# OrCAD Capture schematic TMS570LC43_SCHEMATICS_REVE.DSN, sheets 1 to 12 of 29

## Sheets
1 PAGE08: MCU NHET: size B; title: TMS570LC43x HDK; rev: B; company: Texas Instruments Inc; note: MCU NHET
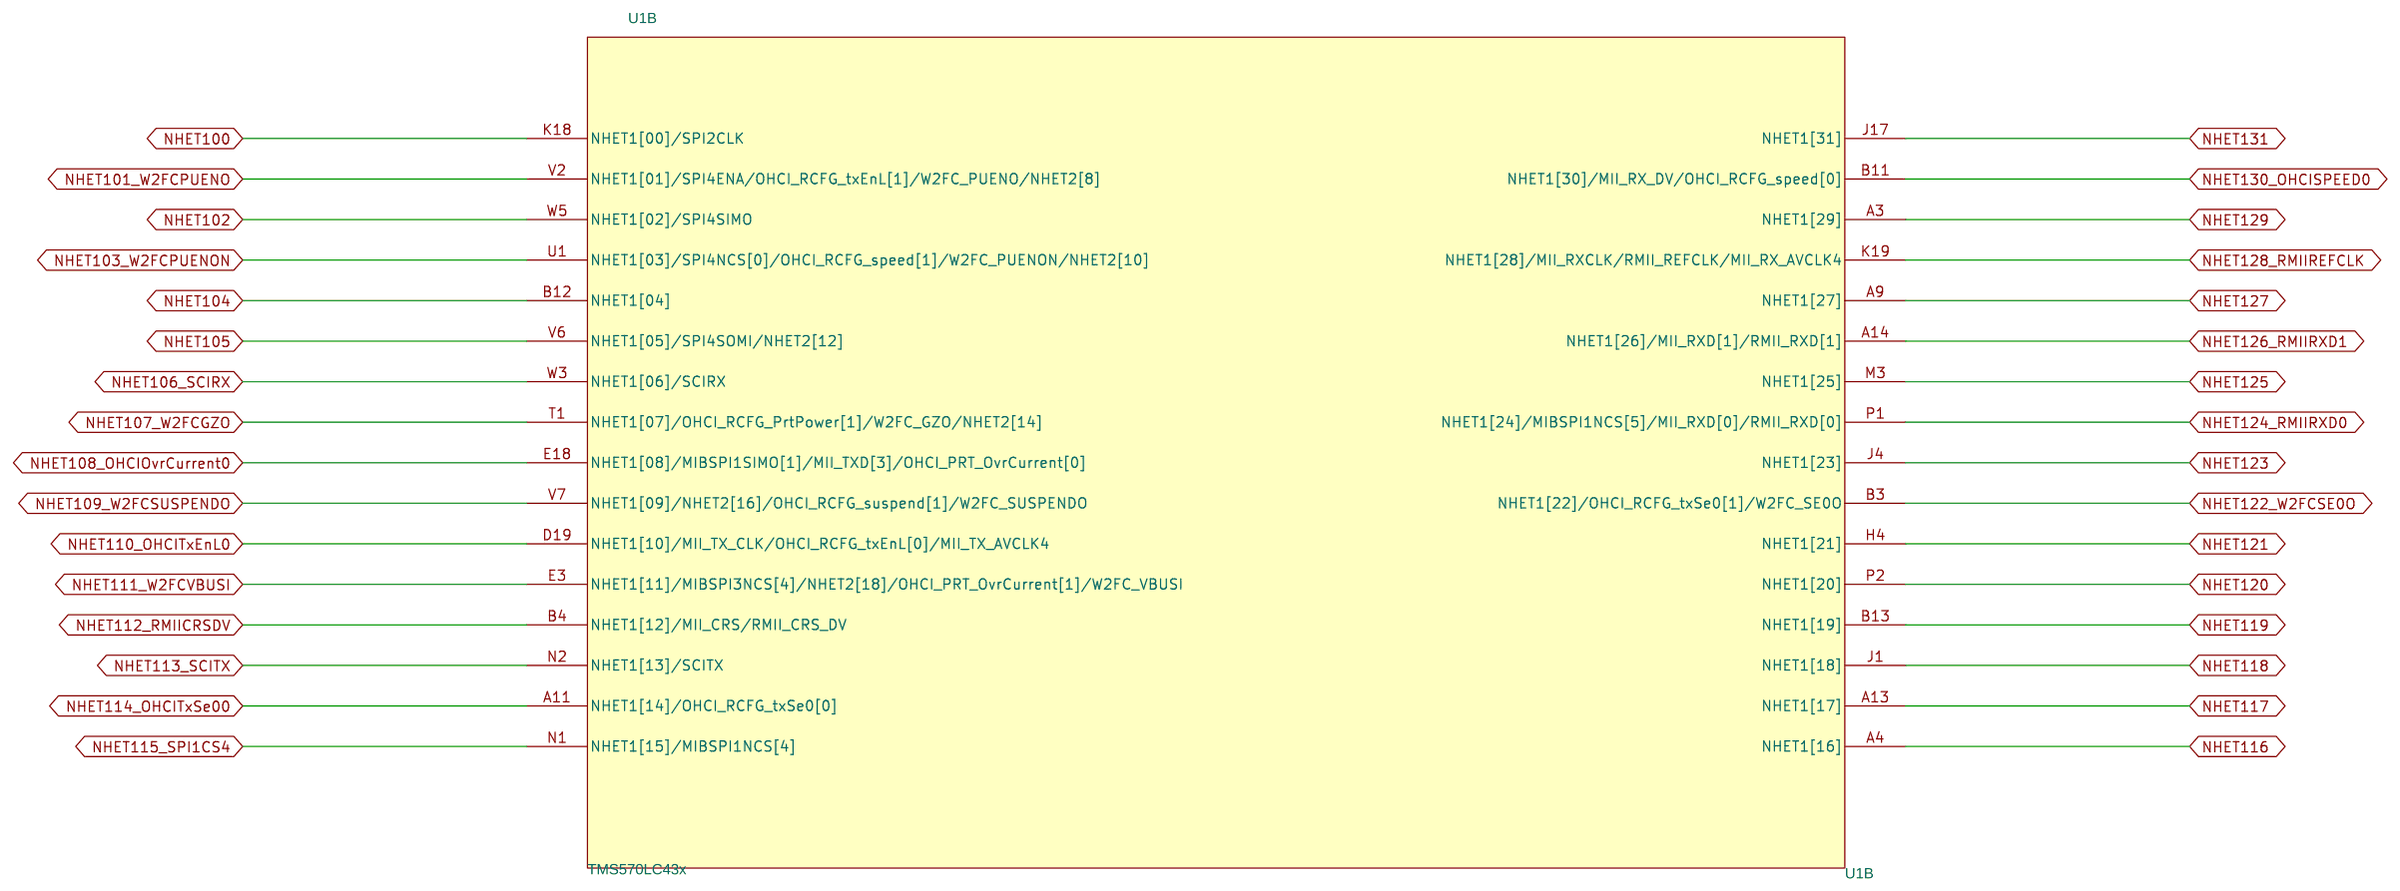
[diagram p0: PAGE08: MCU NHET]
2 PAGE29: EXP P3: size B; note: Expansion Connector 2
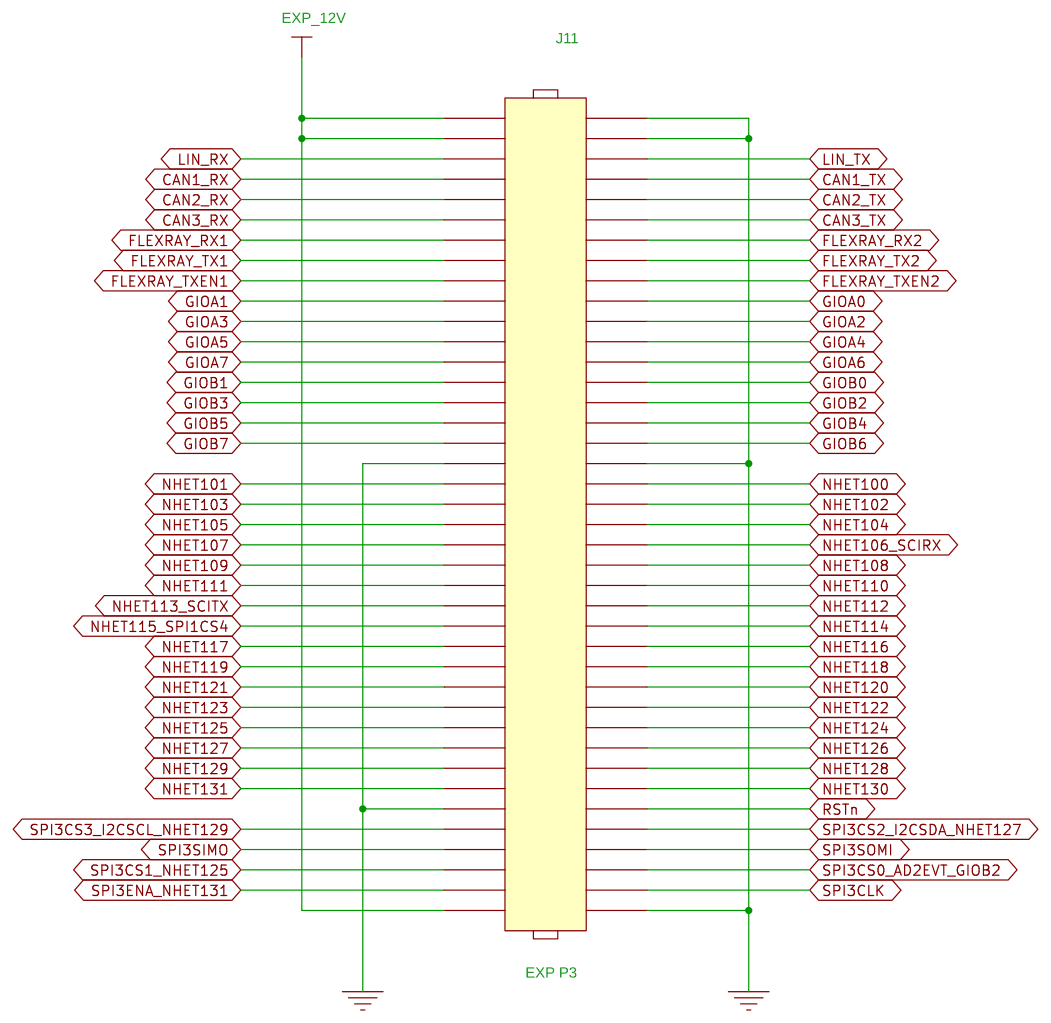
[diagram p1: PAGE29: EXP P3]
3 PAGE13: SDRAM: size B; note: SDRAM
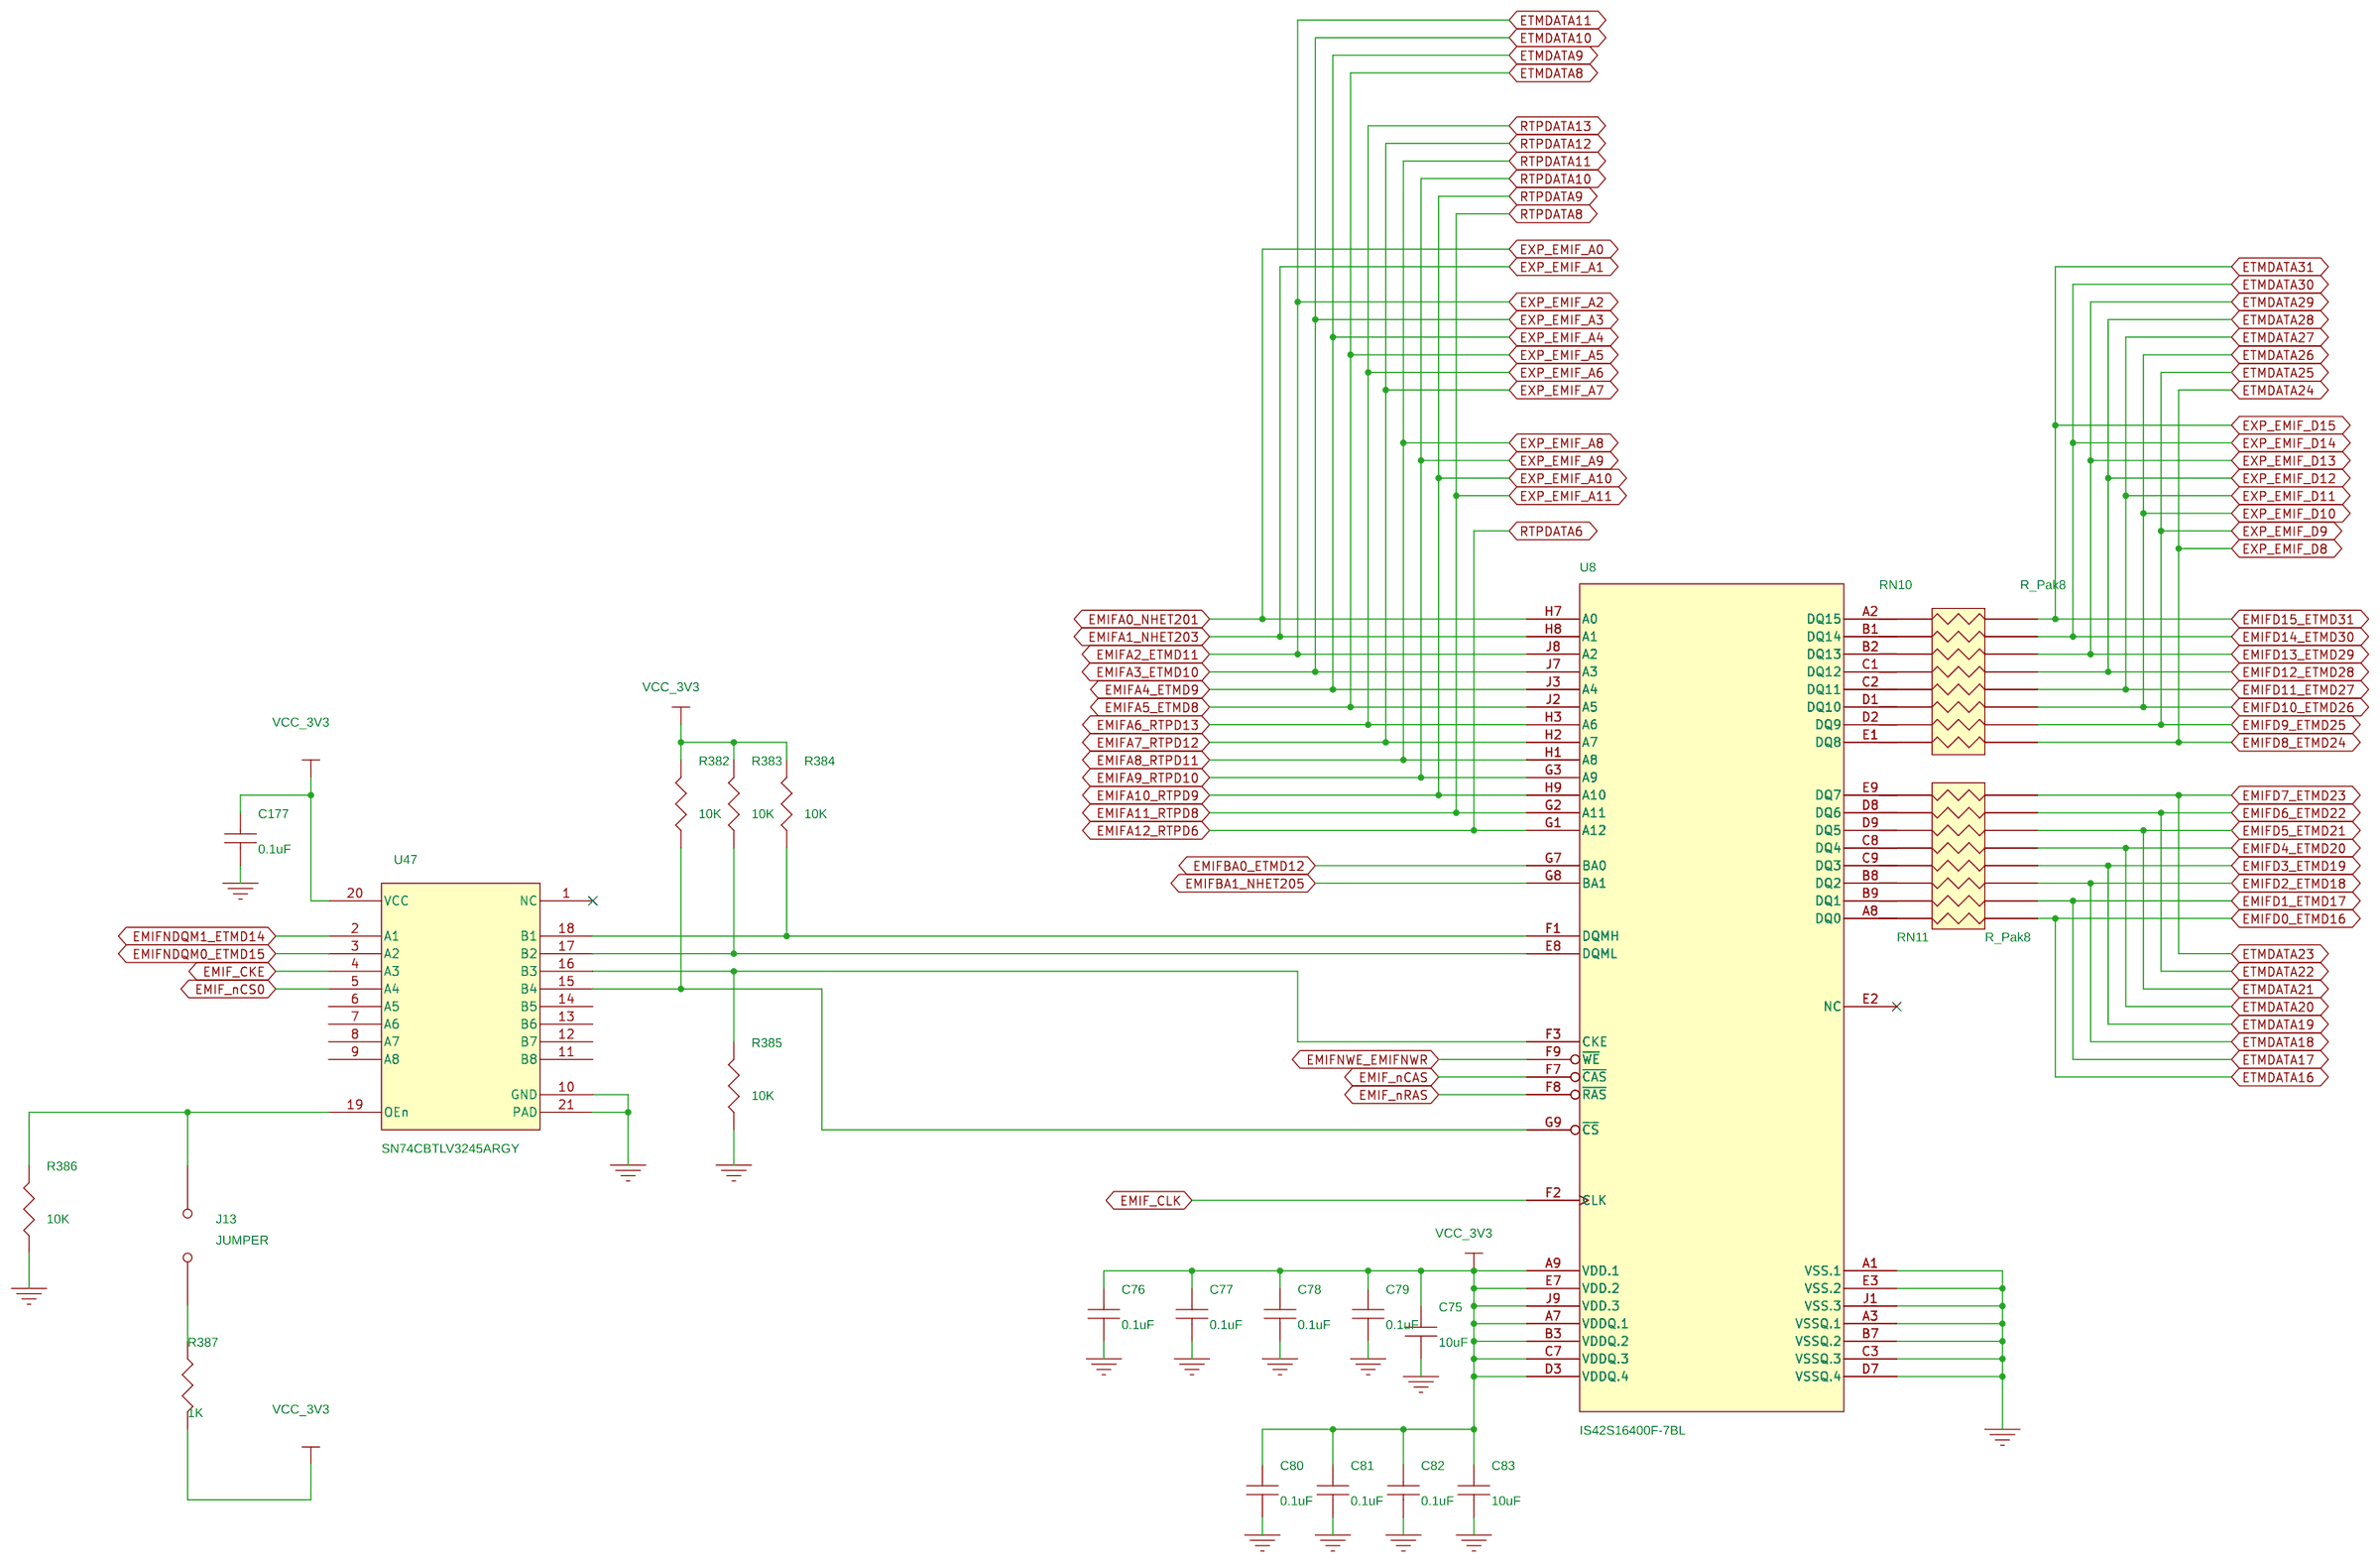
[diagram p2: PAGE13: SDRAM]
4 PAGE01: Title: note: TITLE
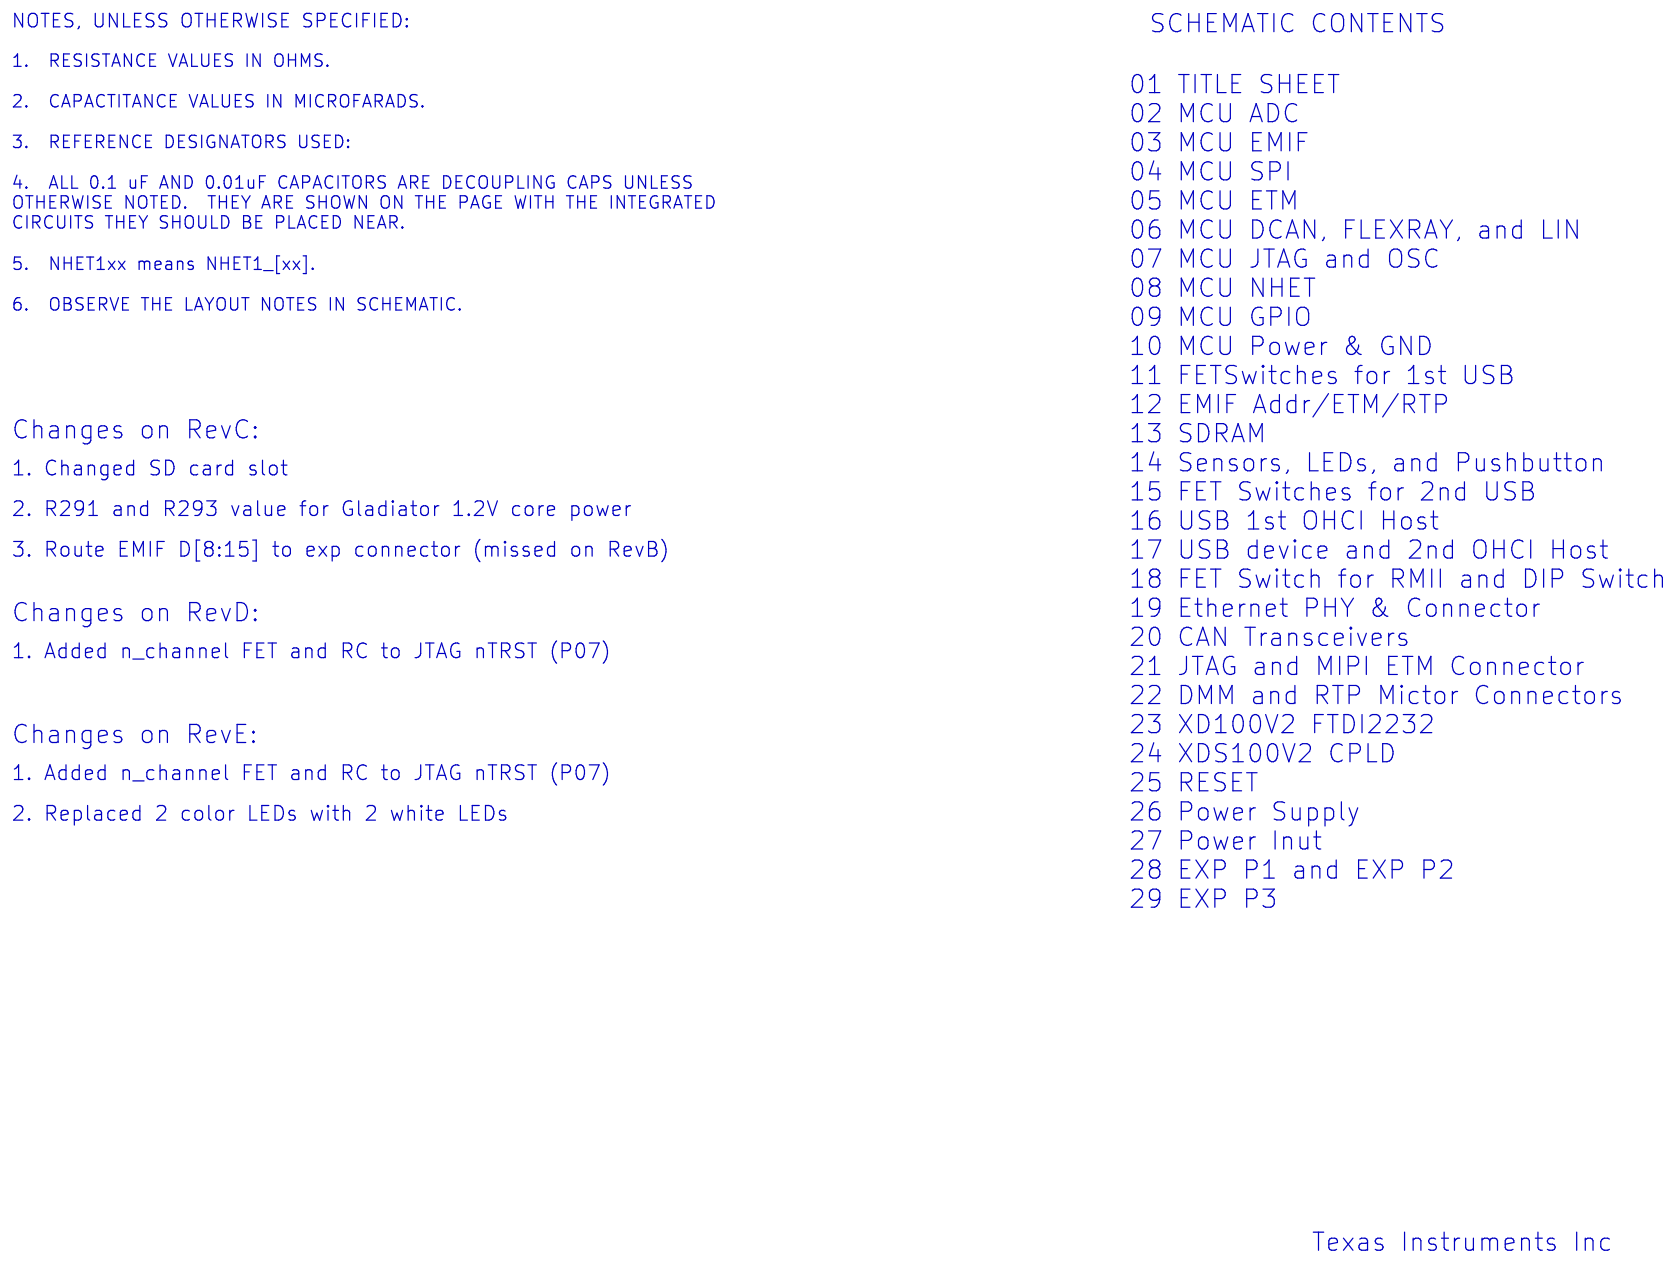
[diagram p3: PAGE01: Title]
5 PAGE25: RESET: size B; note: RESET
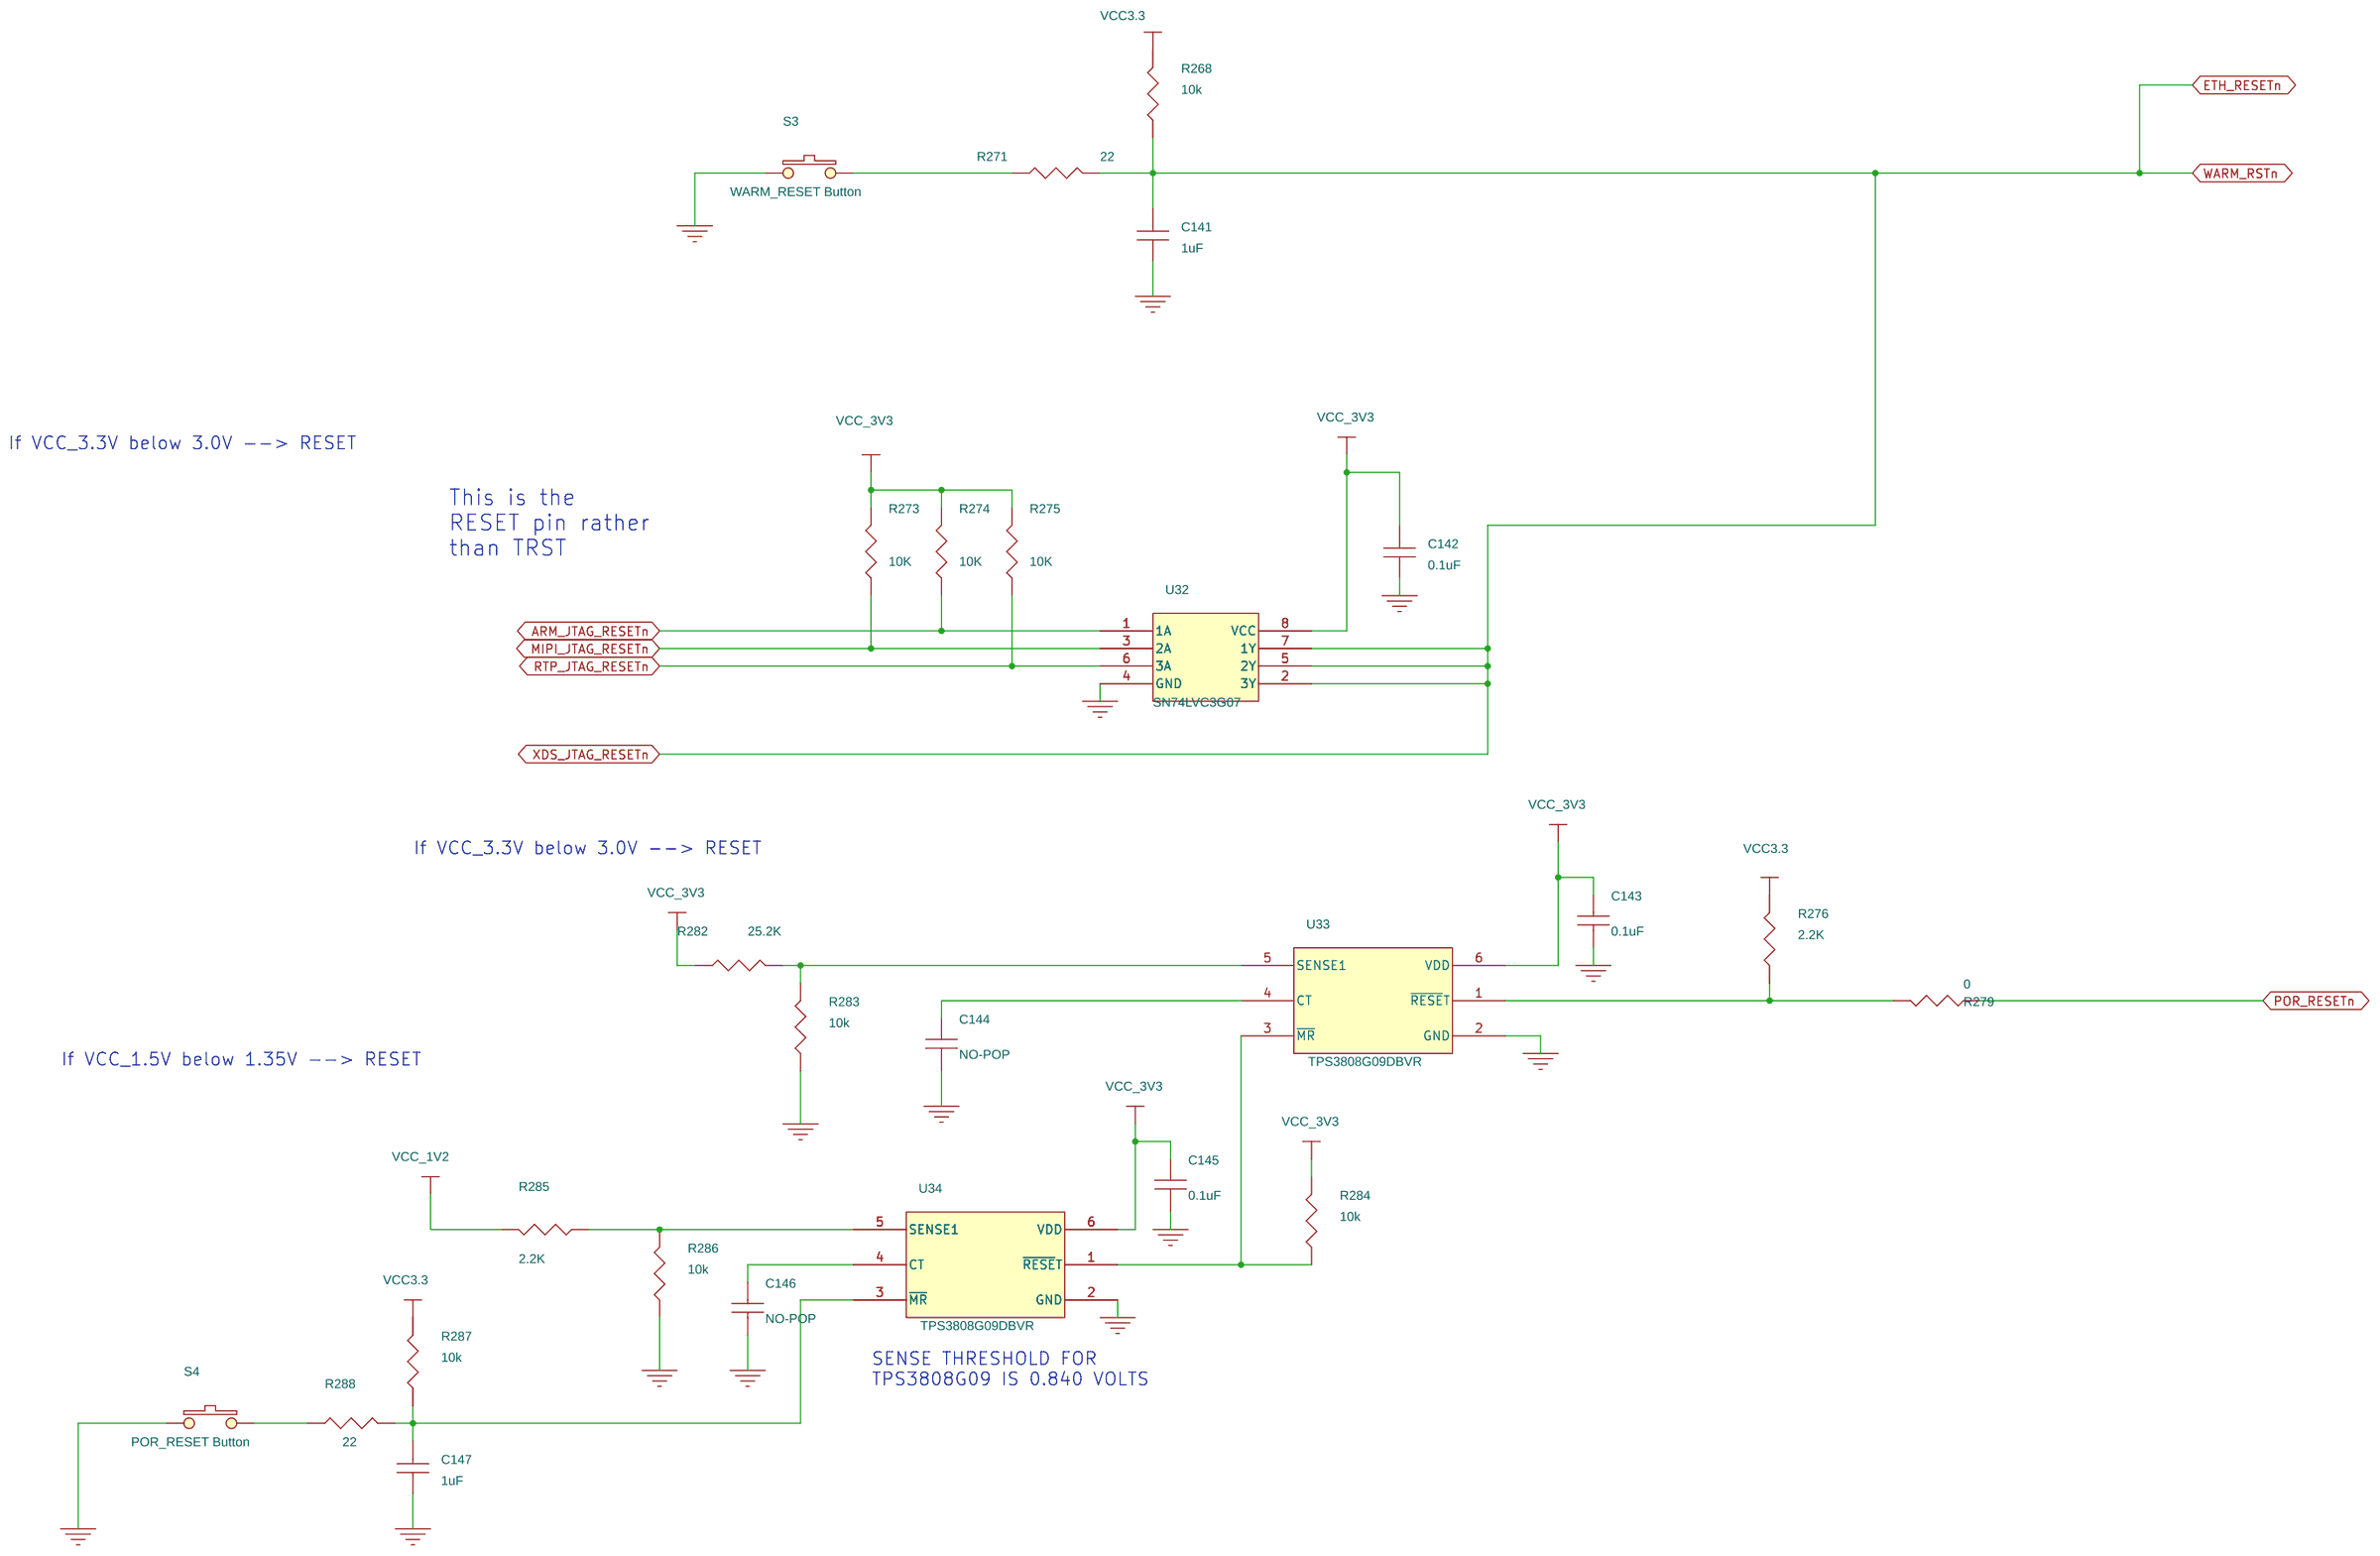
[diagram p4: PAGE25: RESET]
6 PAGE02: MCU  ADC: size B; note: MCU ADC
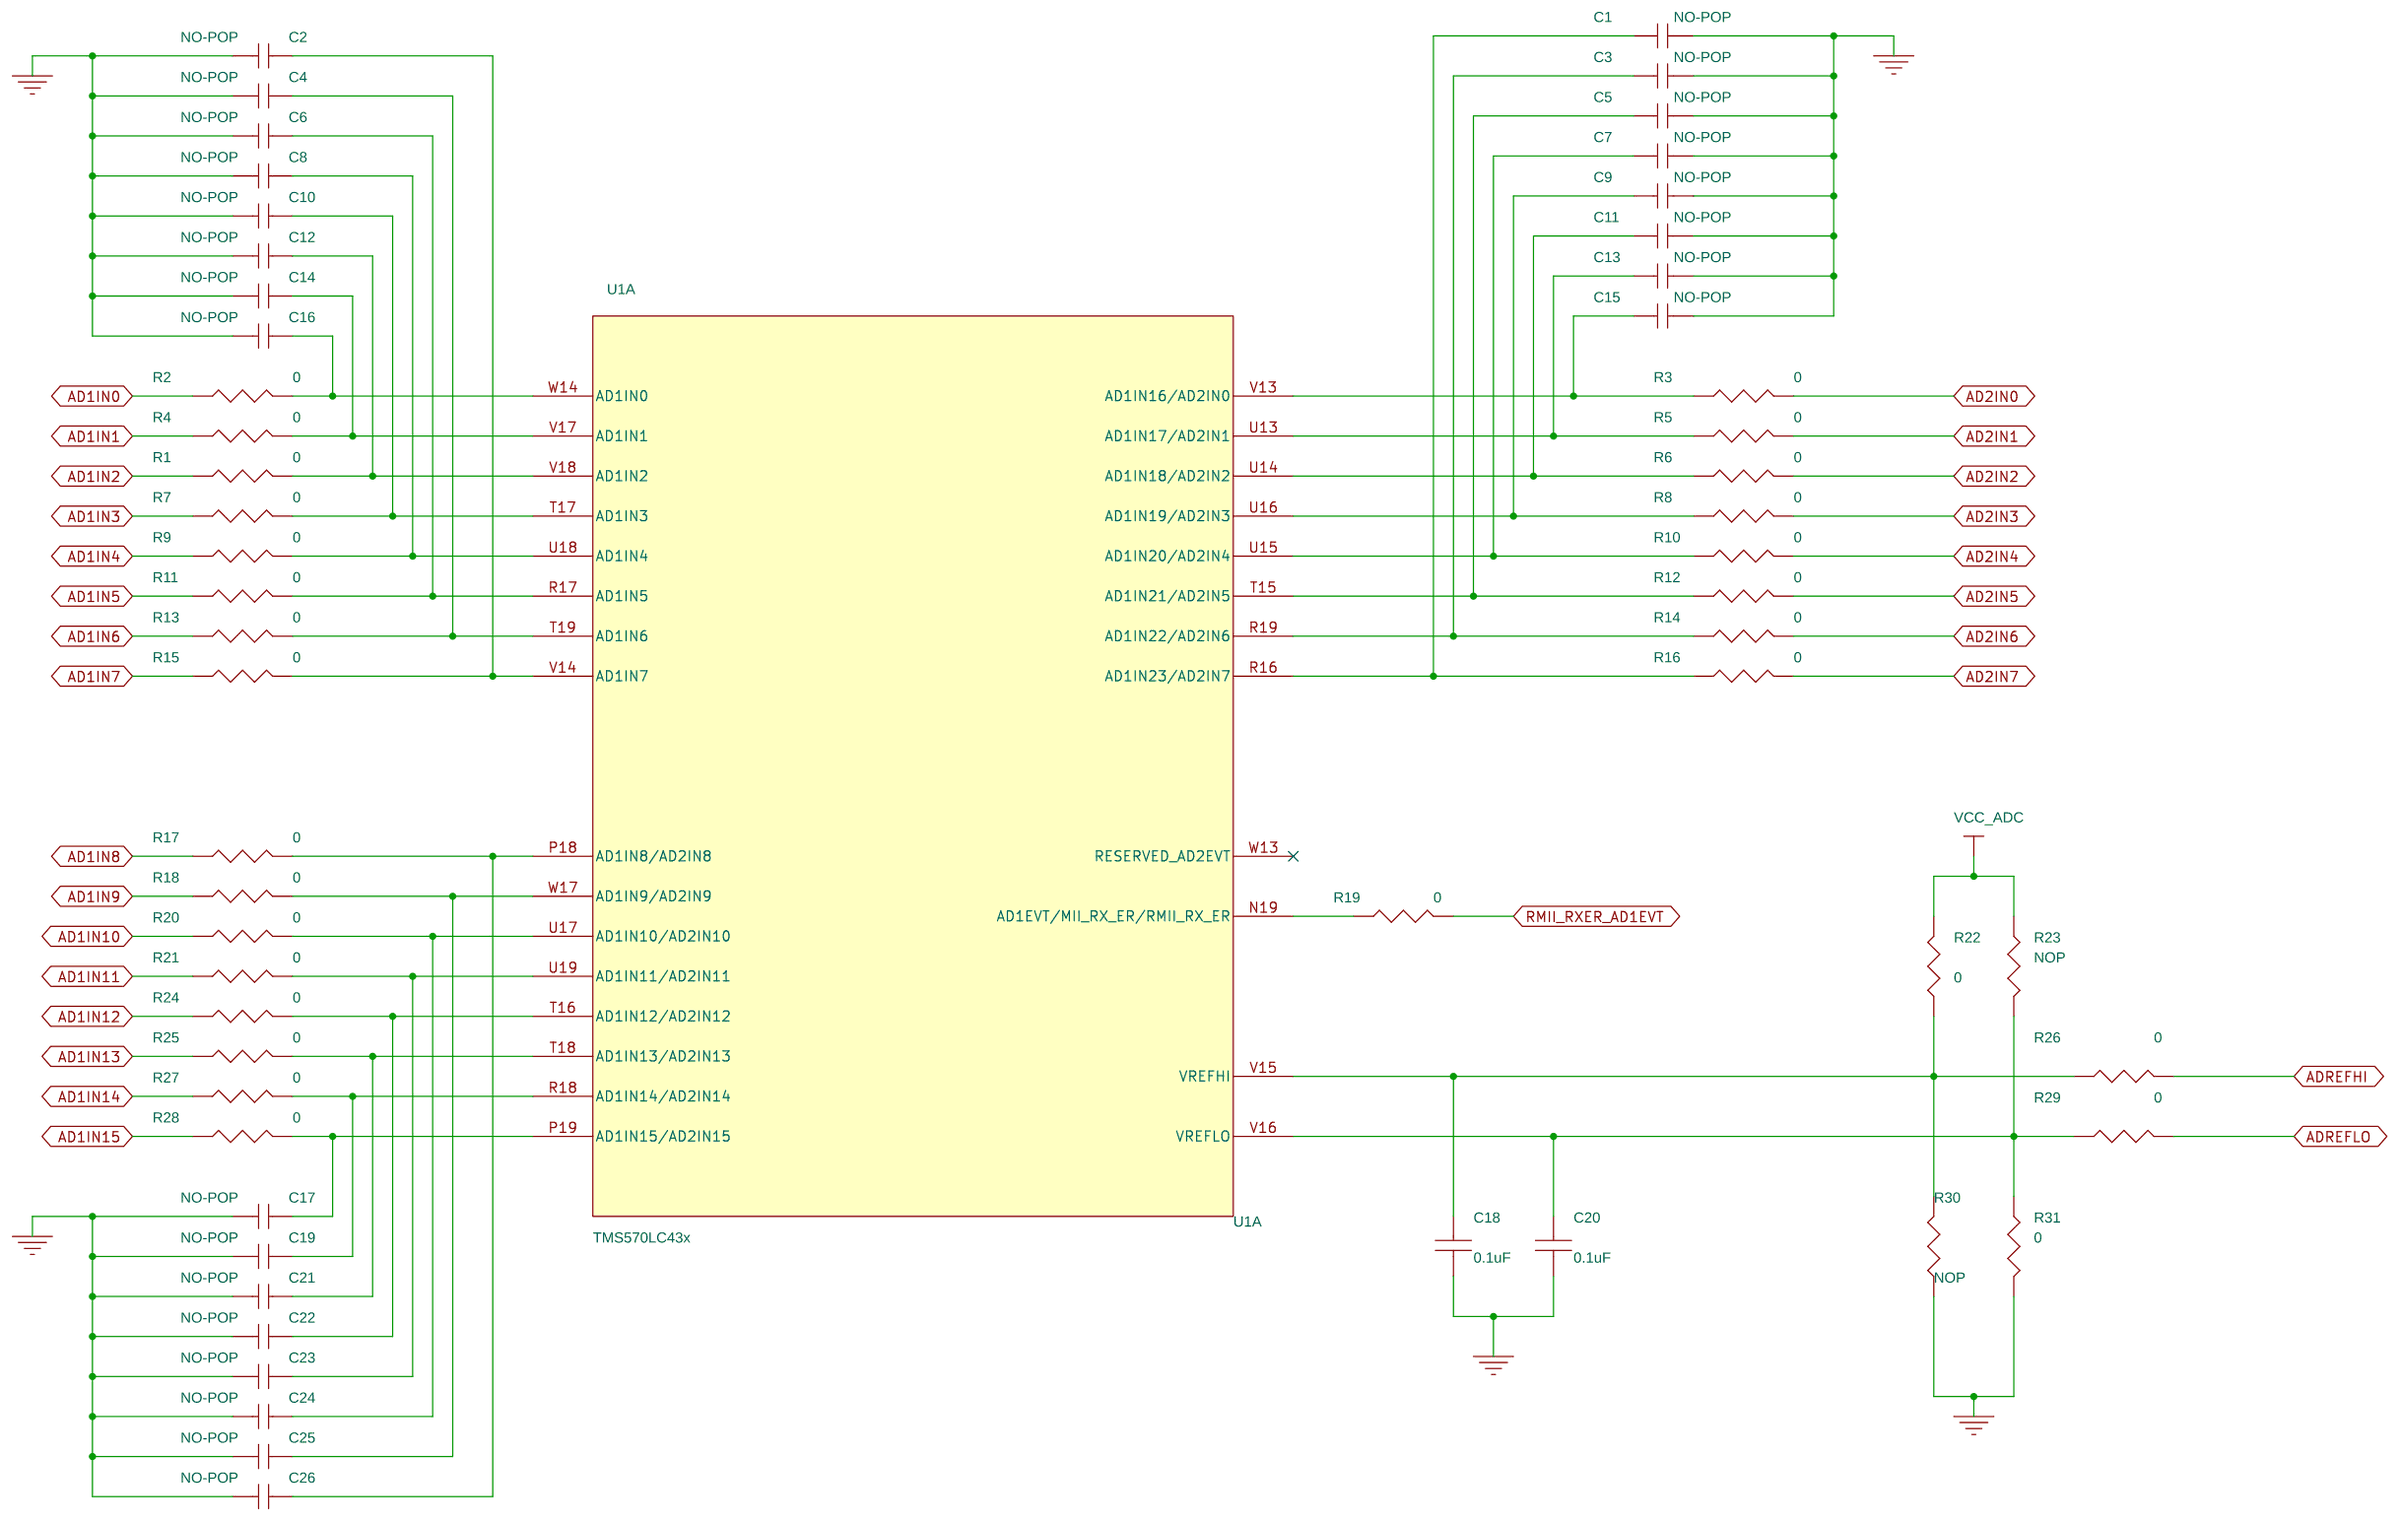
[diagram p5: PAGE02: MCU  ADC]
7 PAGE04: MCU SPI: size B; note: MCU MibSPIs
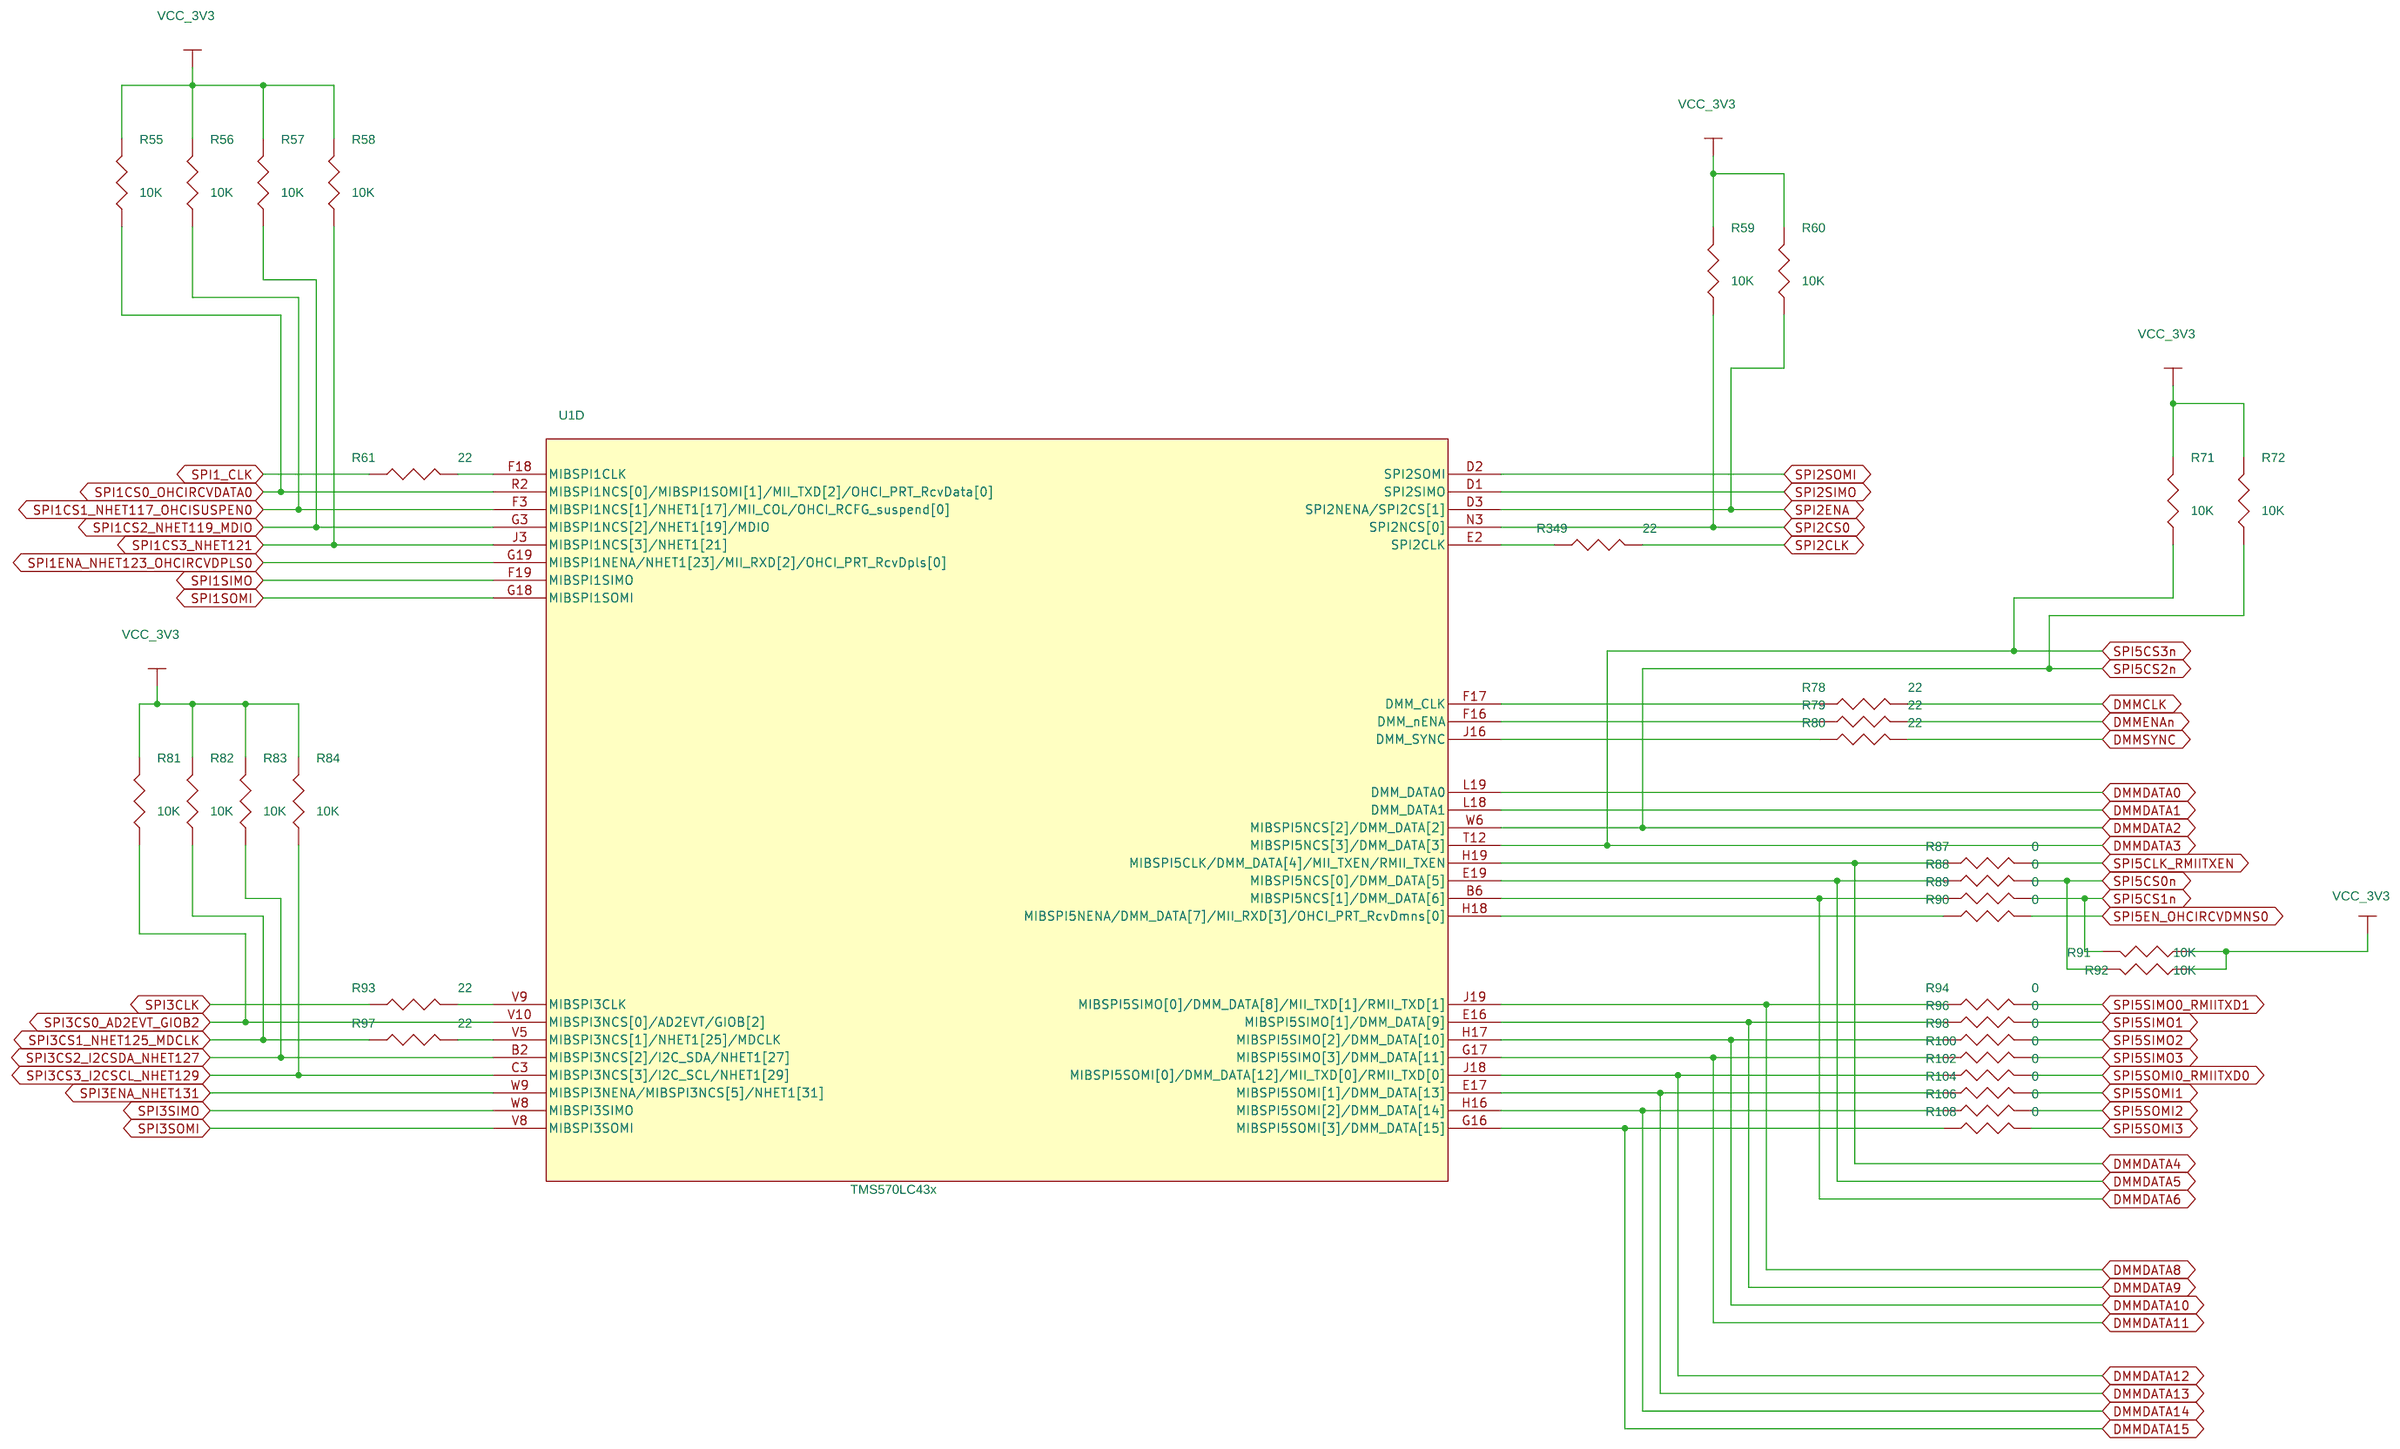
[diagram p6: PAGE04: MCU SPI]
8 PAGE03: MCU EMIF: size B; note: MCU EMIF
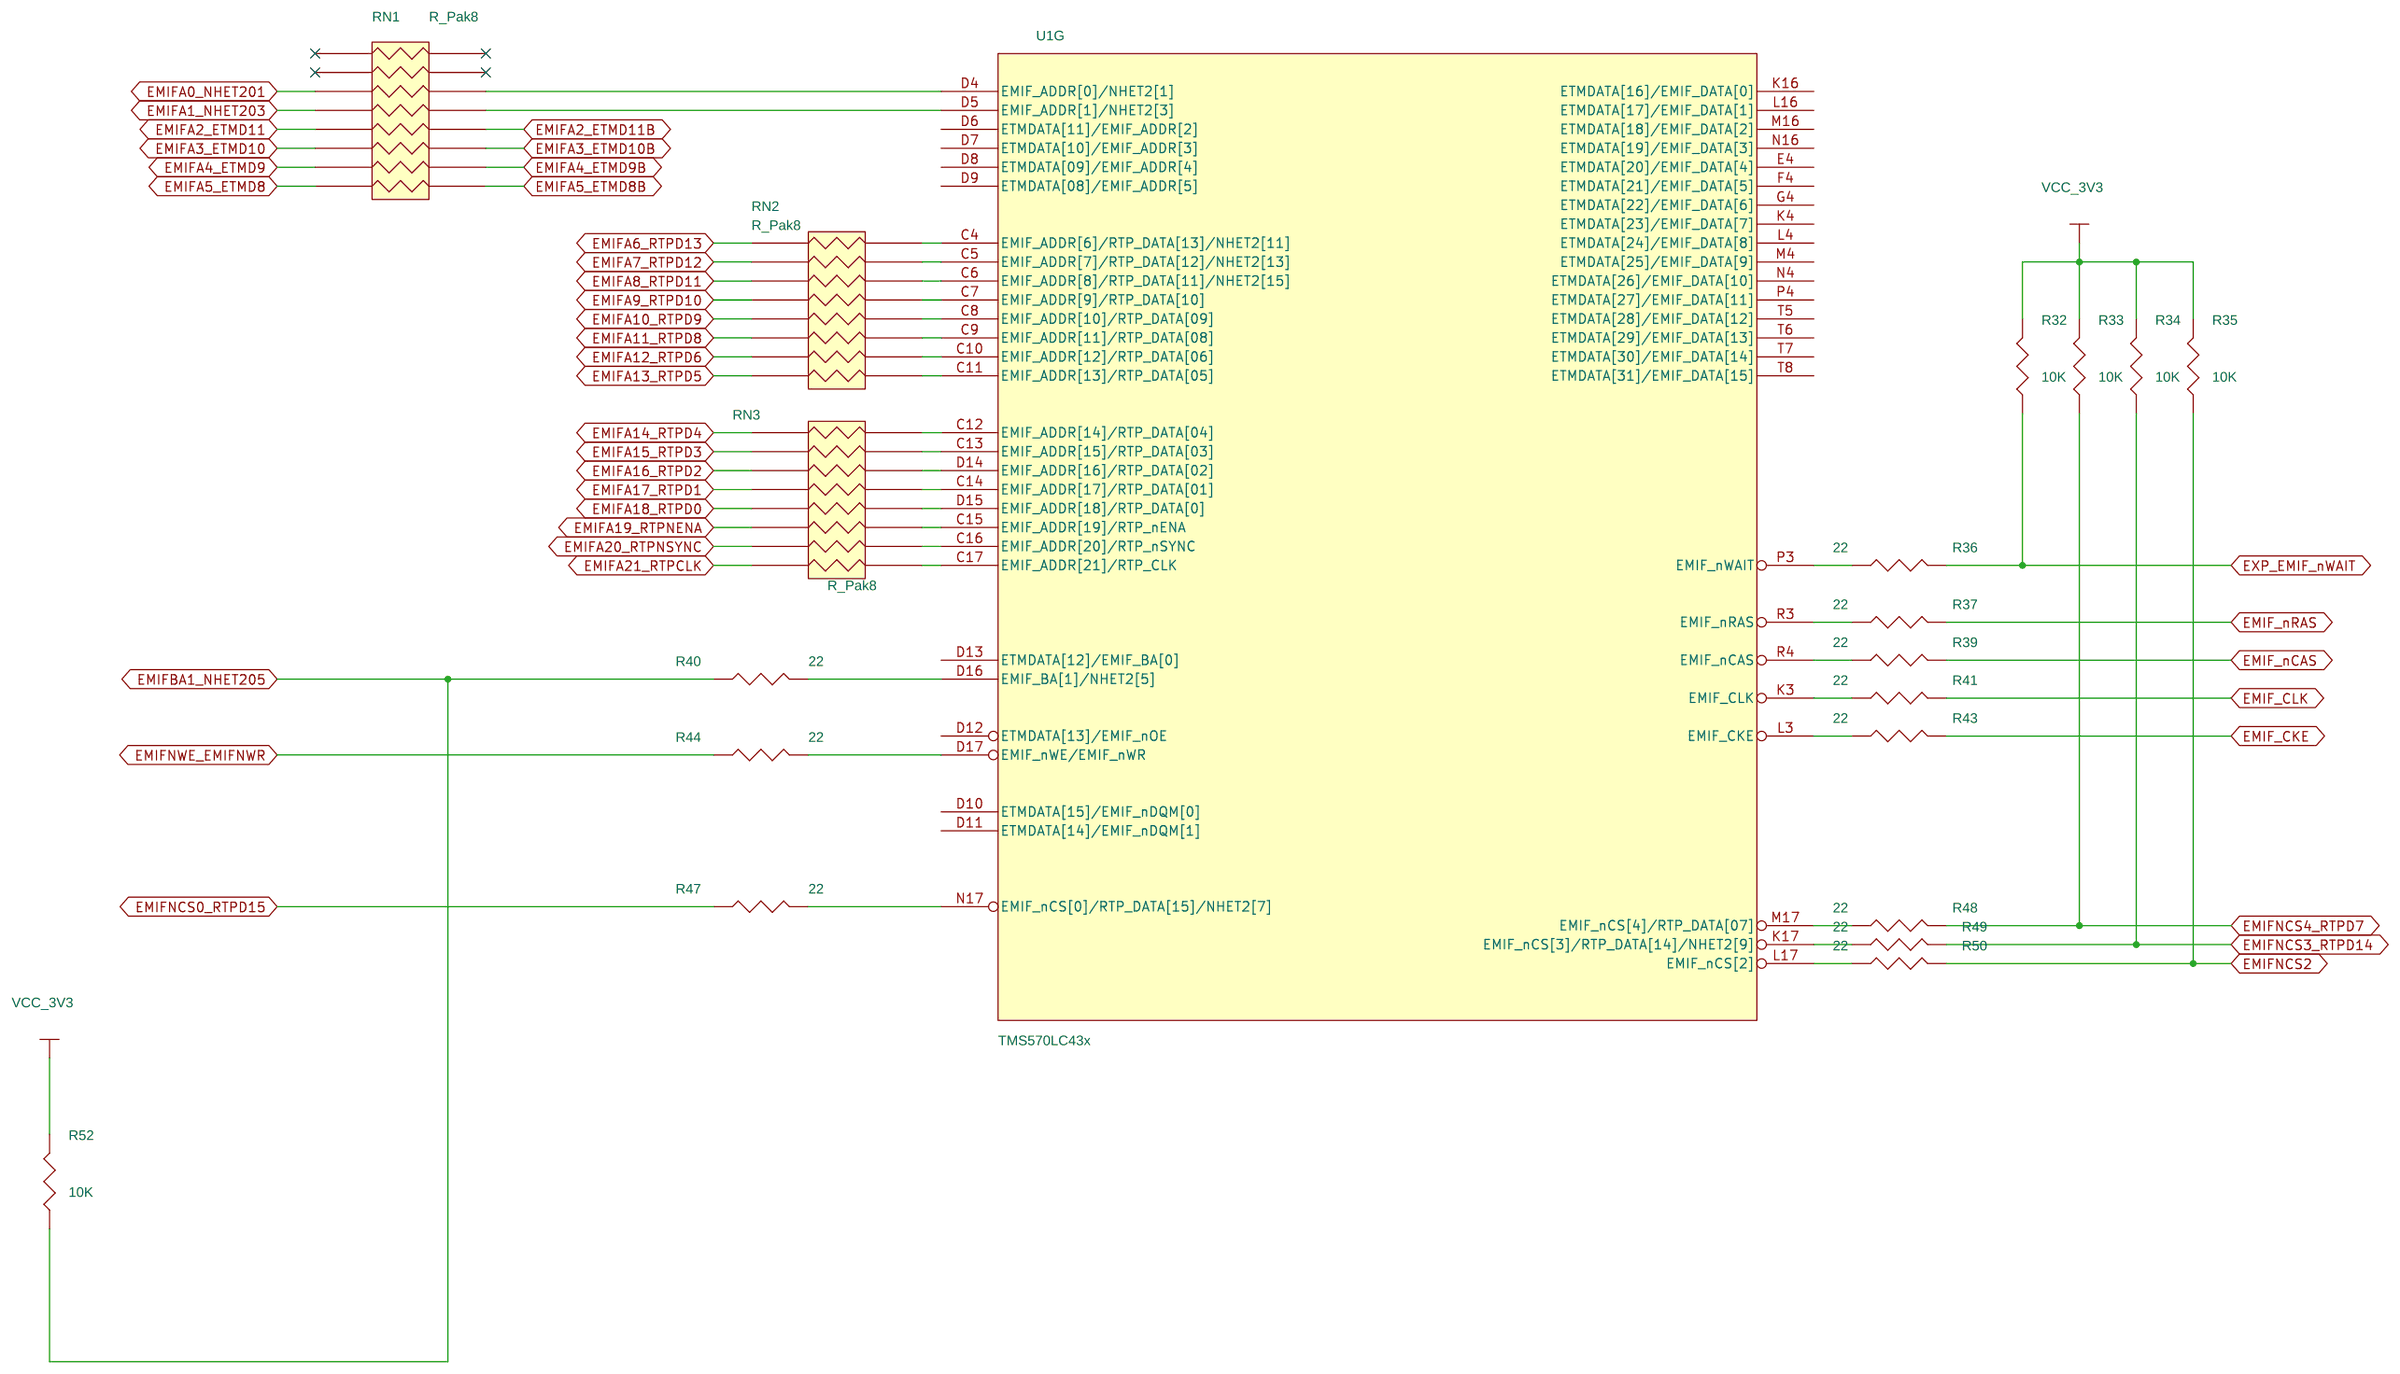
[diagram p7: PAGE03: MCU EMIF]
9 PAGE14: SENSOR, LED, PB: size B; rev: C; note: SENSOR, LED, PB
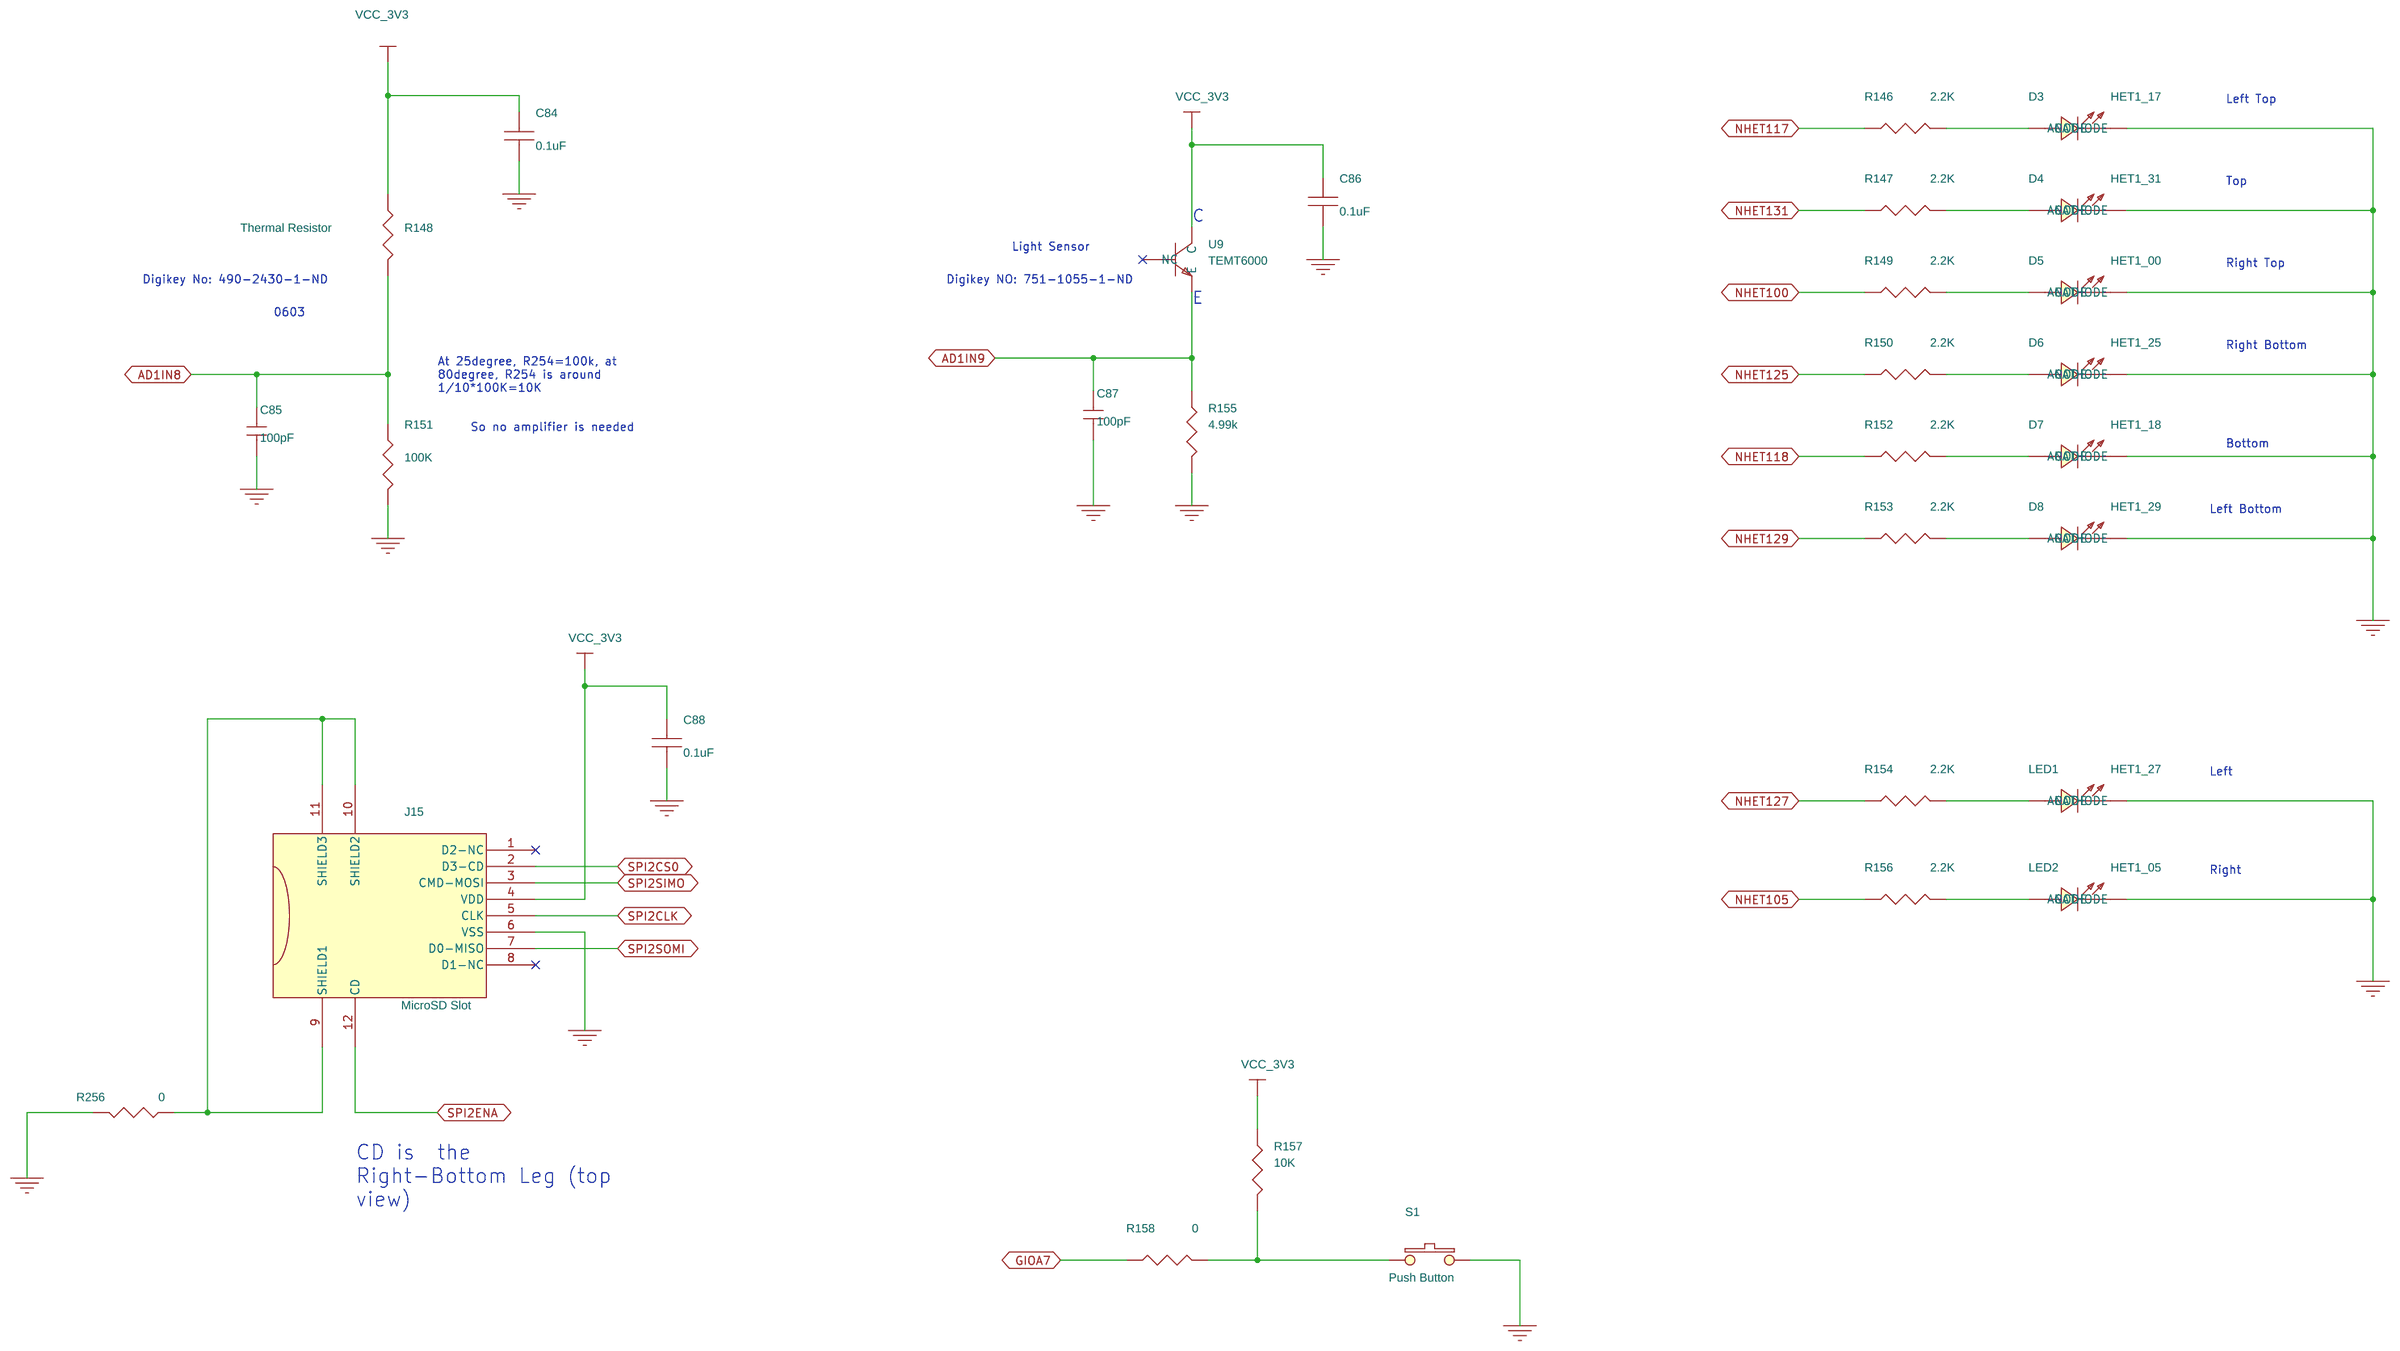
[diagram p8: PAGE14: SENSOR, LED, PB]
10 PAGE26: Power Supply: size B; rev: C; note: Power Supply
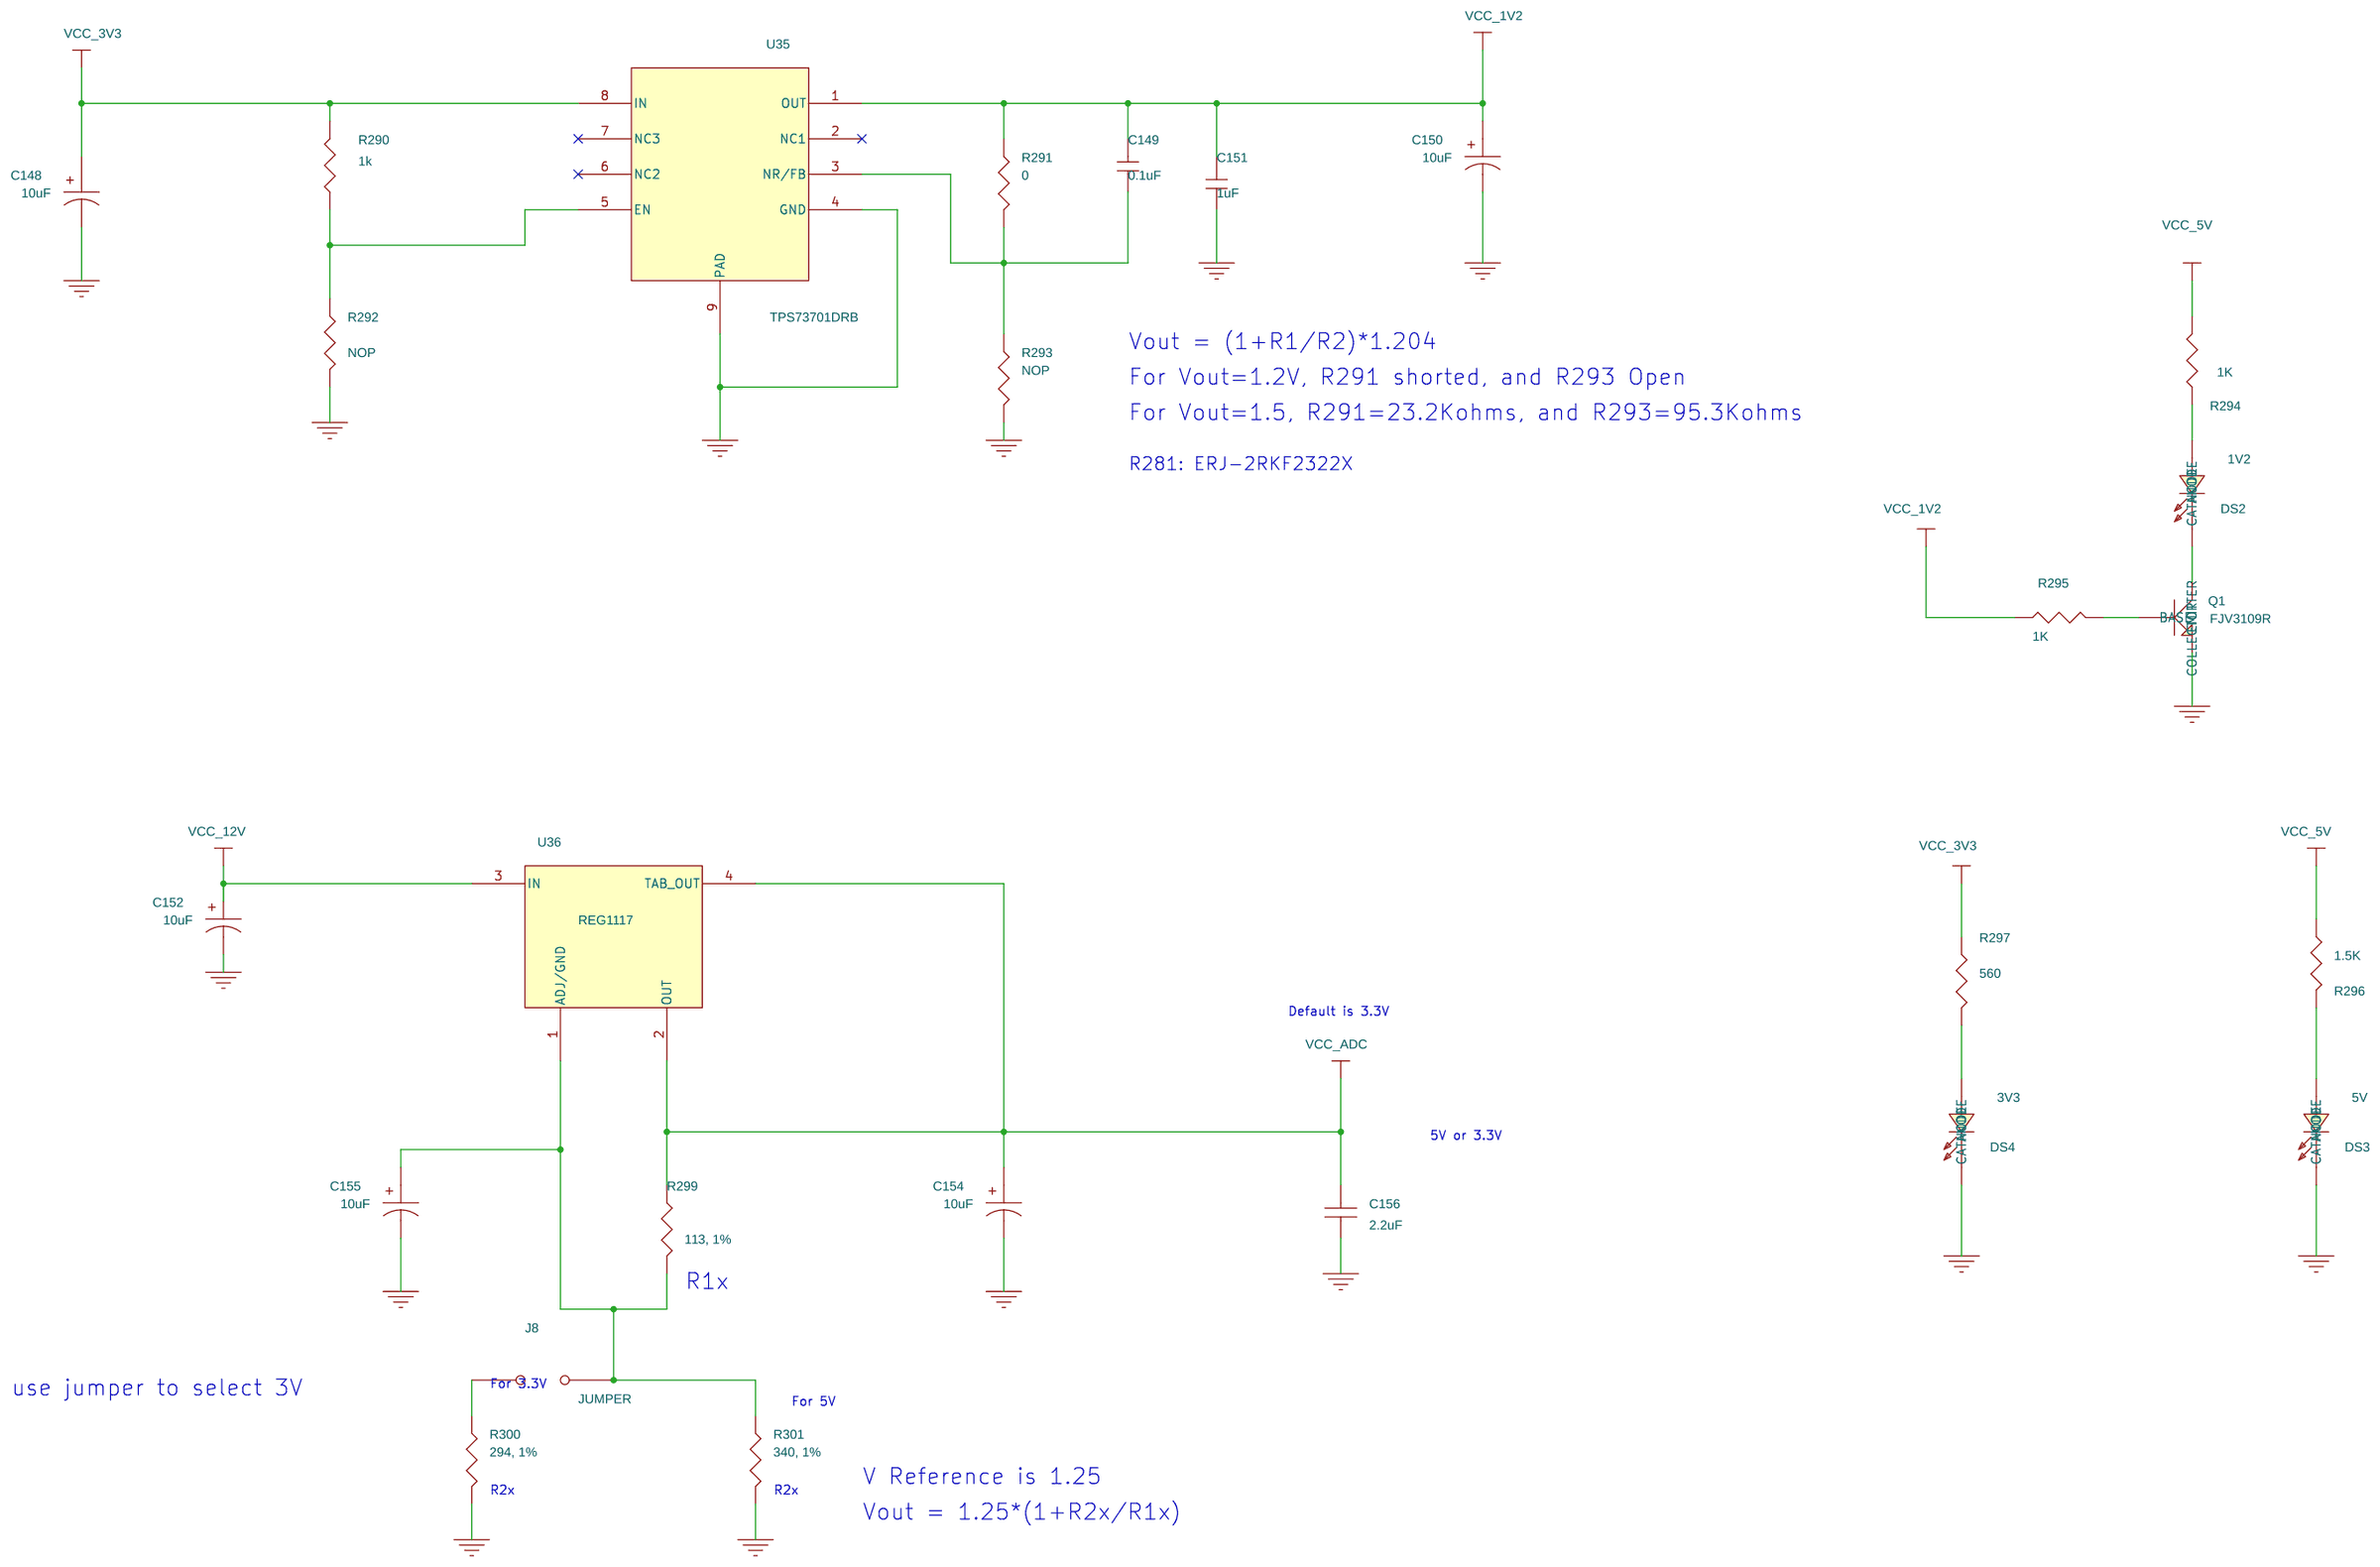
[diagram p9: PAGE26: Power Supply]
11 PAGE22: DMM and RTP: size B; title: TMS570LS3x/RM5x CPU CARD; note: DMM and RTP Connectors
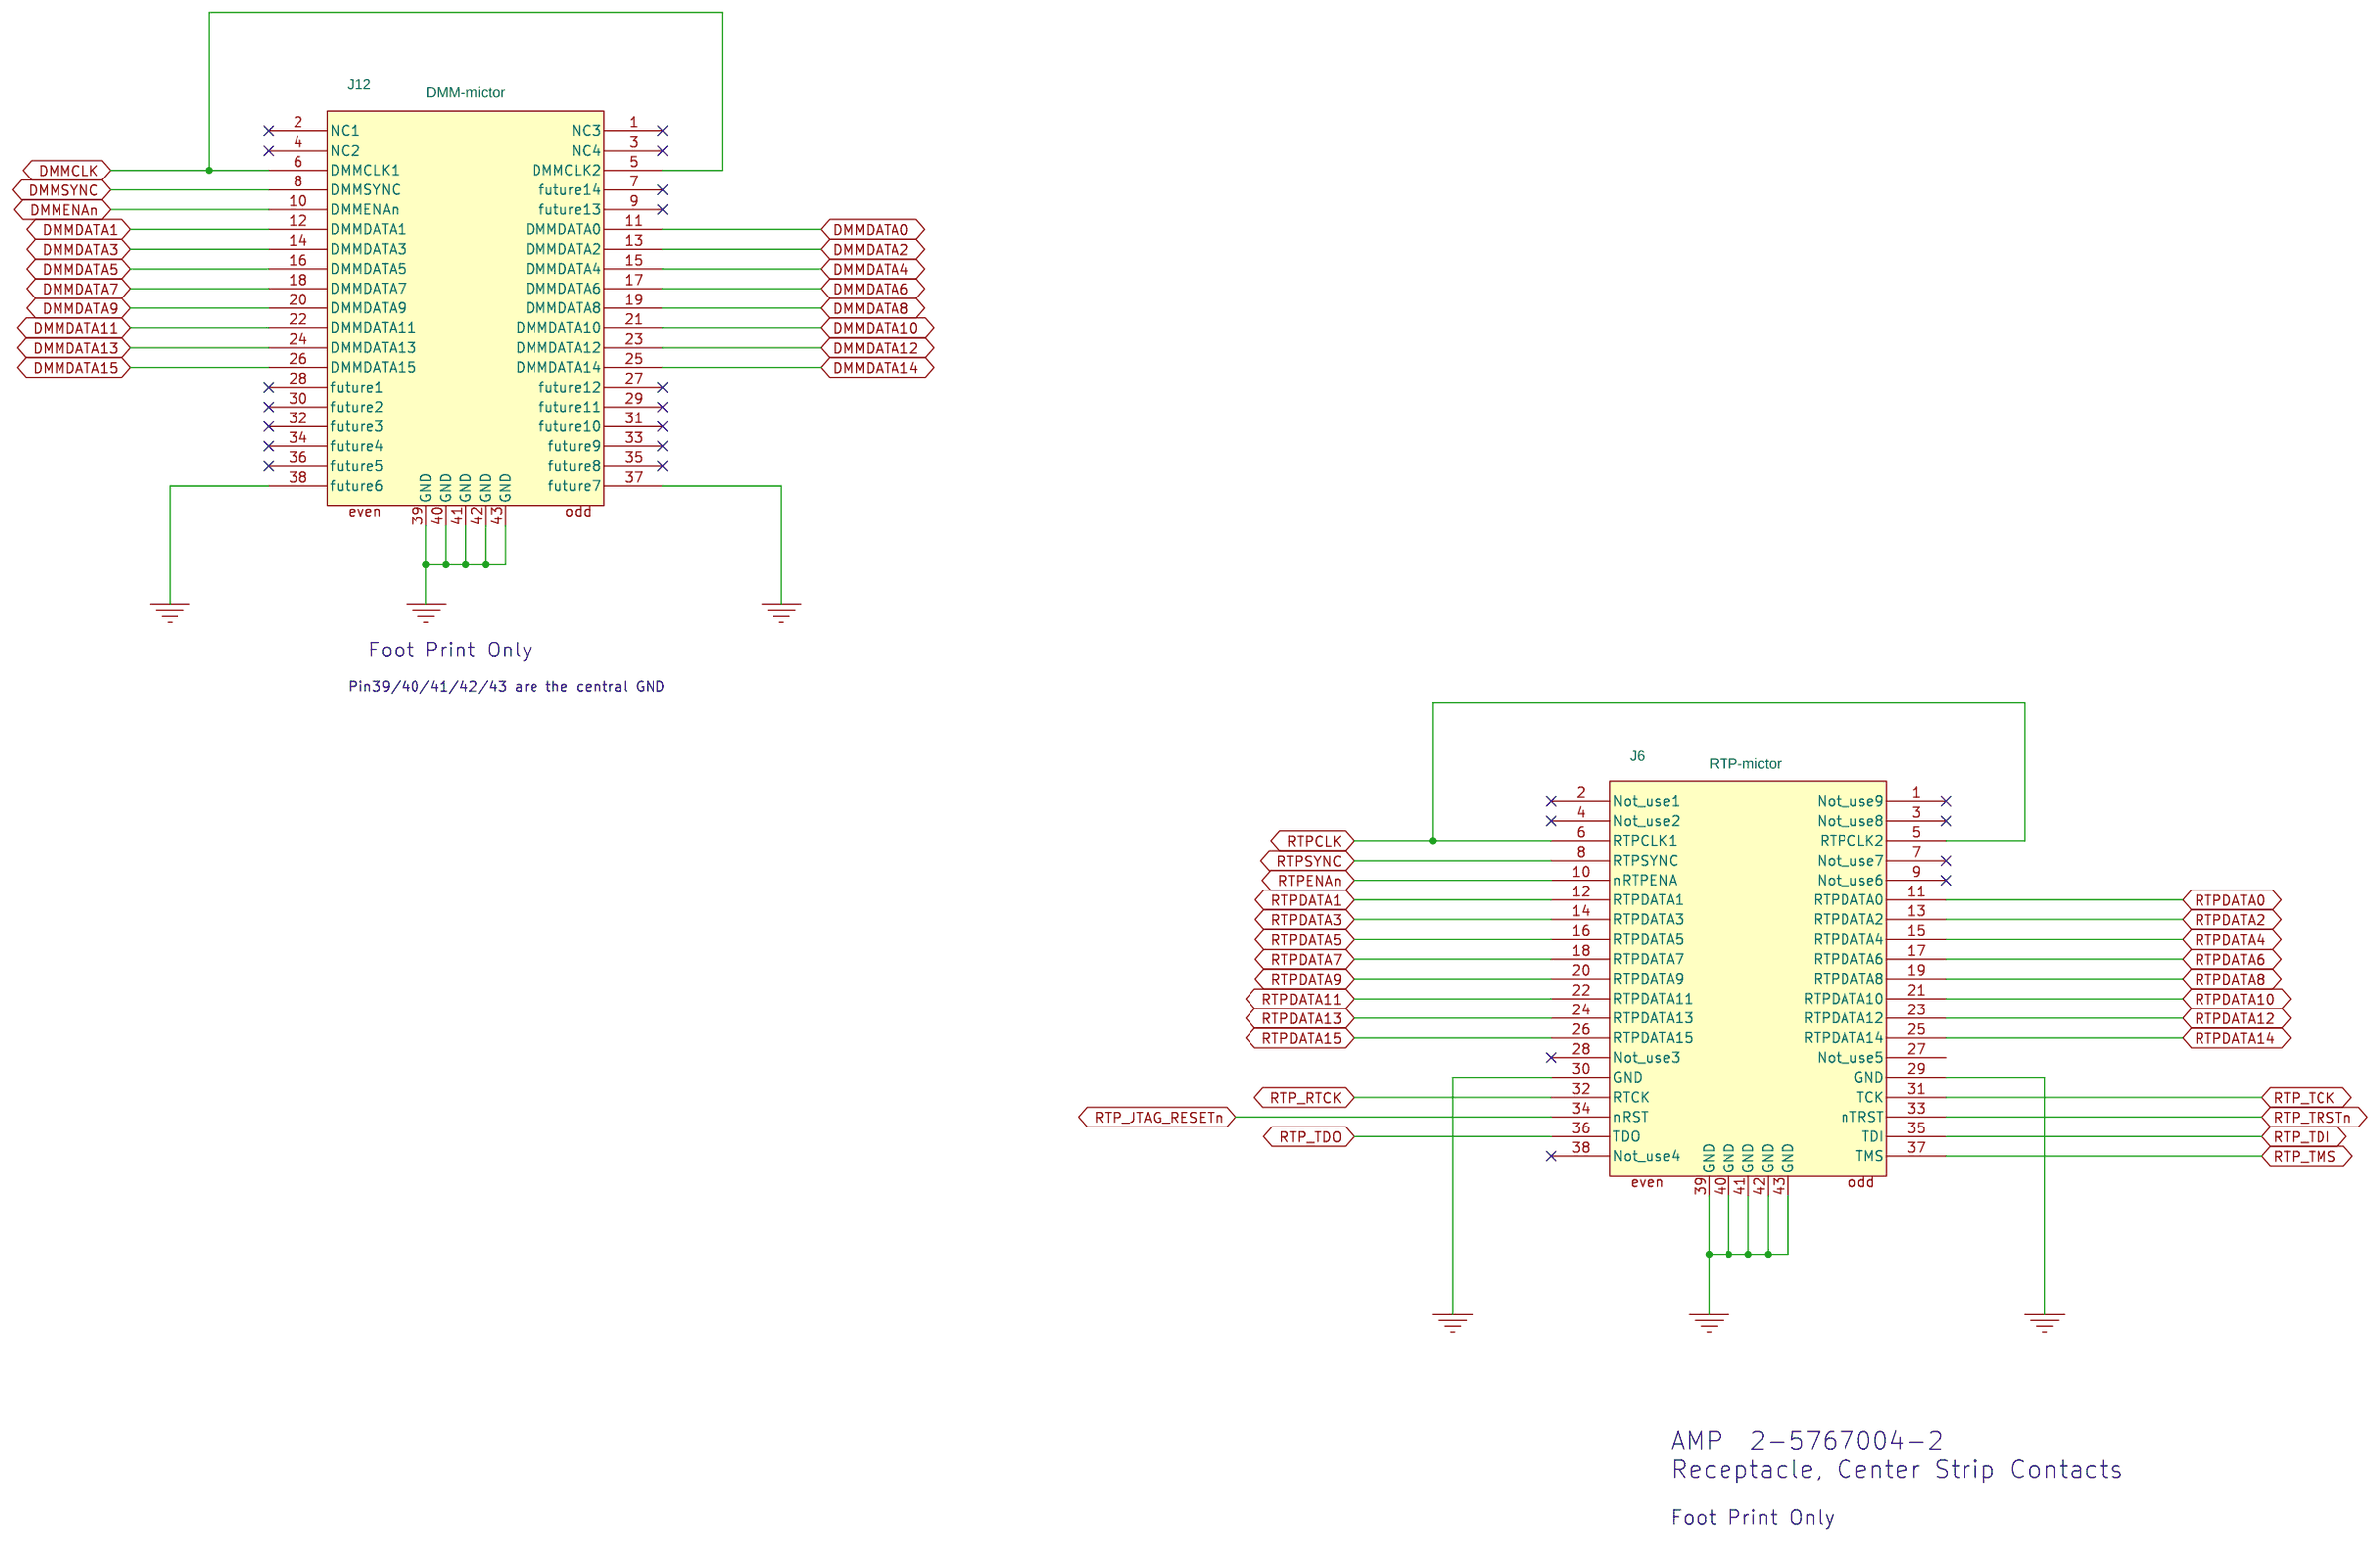
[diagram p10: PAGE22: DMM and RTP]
12 PAGE09: MCU GPIO: size B; note: MCU GPIO
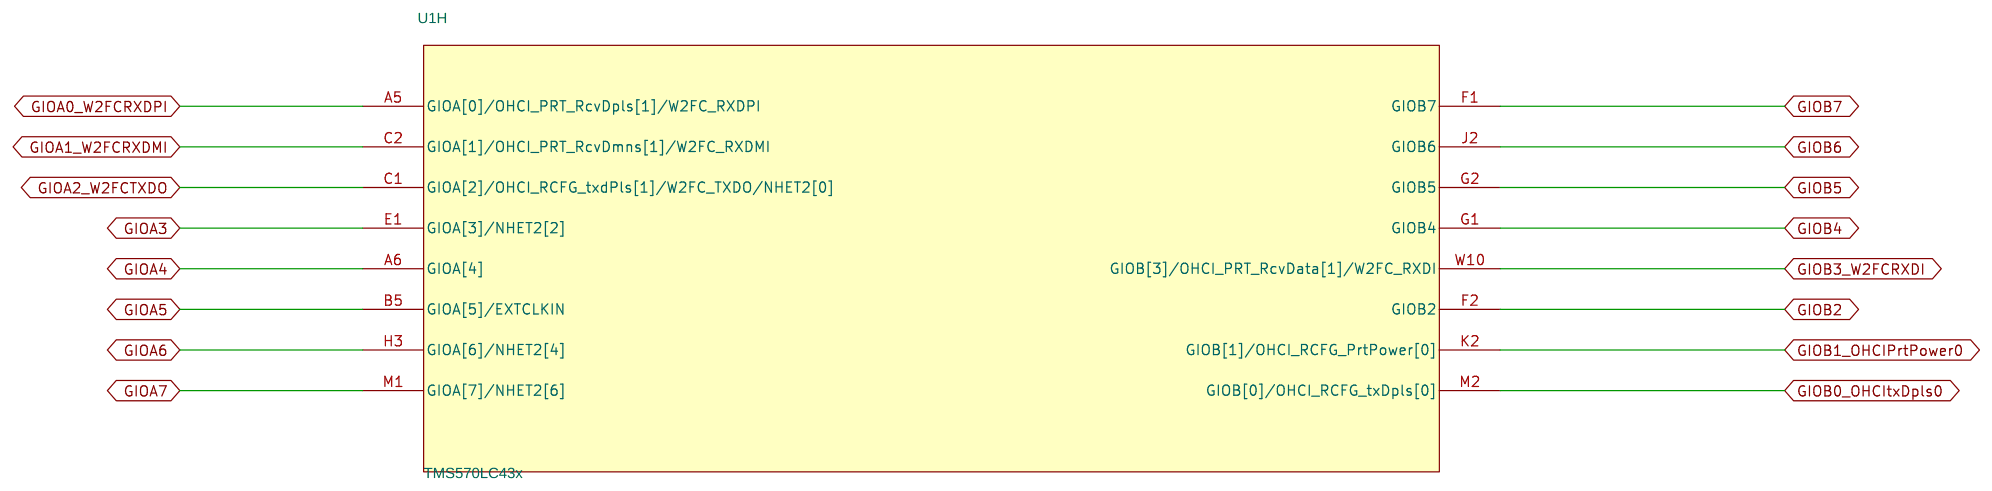
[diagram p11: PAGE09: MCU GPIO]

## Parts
sheet PAGE02: MCU  ADC
C1  NO-POP  [c0402]
C2  NO-POP  [c0402]
C3  NO-POP  [c0402]
C4  NO-POP  [c0402]
C5  NO-POP  [c0402]
C6  NO-POP  [c0402]
C7  NO-POP  [c0402]
C8  NO-POP  [c0402]
C9  NO-POP  [c0402]
C10  NO-POP  [c0402]
C11  NO-POP  [c0402]
C12  NO-POP  [c0402]
C13  NO-POP  [c0402]
C14  NO-POP  [c0402]
C15  NO-POP  [c0402]
C16  NO-POP  [c0402]
C17  NO-POP  [c0402]
C18  0.1uF  [c0402]
C19  NO-POP  [c0402]
C20  0.1uF  [c0402]
C21  NO-POP  [c0402]
C22  NO-POP  [c0402]
C23  NO-POP  [c0402]
C24  NO-POP  [c0402]
C25  NO-POP  [c0402]
C26  NO-POP  [c0402]
R1  0  [r0402]
R2  0  [r0402]
R3  0  [r0402]
R4  0  [r0402]
R5  0  [r0402]
R6  0  [r0402]
R7  0  [r0402]
R8  0  [r0402]
R9  0  [r0402]
R10  0  [r0402]
R11  0  [r0402]
R12  0  [r0402]
R13  0  [r0402]
R14  0  [r0402]
R15  0  [r0402]
R16  0  [r0402]
R17  0  [r0402]
R18  0  [r0402]
R19  0  [r0402]
R20  0  [r0402]
R21  0  [r0402]
R22  0  [r0402]
R23  NOP  [r0402]
R24  0  [r0402]
R25  0  [r0402]
R26  0  [r0402]
R27  0  [r0402]
R28  0  [r0402]
R29  0  [r0402]
R30  NOP  [r0402]
R31  0  [r0402]
sheet PAGE03: MCU EMIF
R32  10K  [r0402]
R33  10K  [r0402]
R34  10K  [r0402]
R35  10K  [r0402]
R36  22  [r0402]
R37  22  [r0402]
R39  22  [r0402]
R40  22  [r0402]
R41  22  [r0402]
R43  22  [r0402]
R44  22  [r0402]
R47  22  [r0402]
R48  22  [r0402]
R49  22  [r0402]
R50  22  [r0402]
R52  10K  [r0402]
RN1  R_Pak8  [EXB-2HVS]
RN2  R_Pak8  [EXB-2HVS]
RN3  R_Pak8  [EXB-2HVS]
sheet PAGE04: MCU SPI
R55  10K  [r0402]
R56  10K  [r0402]
R57  10K  [r0402]
R58  10K  [r0402]
R59  10K  [r0402]
R60  10K  [r0402]
R61  22  [r0402]
R71  10K  [r0402]
R72  10K  [r0402]
R78  22  [r0402]
R79  22  [r0402]
R80  22  [r0402]
R81  10K  [r0402]
R82  10K  [r0402]
R83  10K  [r0402]
R84  10K  [r0402]
R87  0  [r0402]
R88  0  [r0402]
R89  0  [r0402]
R90  0  [r0402]
R91  10K  [r0402]
R92  10K  [r0402]
R93  22  [r0402]
R94  0  [r0402]
R96  0  [r0402]
R97  22  [r0402]
R98  0  [r0402]
R100  0  [r0402]
R102  0  [r0402]
R104  0  [r0402]
R106  0  [r0402]
R108  0  [r0402]
R349  22  [r0402]
sheet PAGE05: MCU ETM & RSVED_RTP
U1  TMS570LC43x  [BGA337]  (sections A,B,C,D,E,F,G,H,I)
sheet PAGE13: SDRAM
C75  10uF  [c0603]
C76  0.1uF  [c0402]
C77  0.1uF  [c0402]
C78  0.1uF  [c0402]
C79  0.1uF  [c0402]
C80  0.1uF  [c0402]
C81  0.1uF  [c0402]
C82  0.1uF  [c0402]
C83  10uF  [c0603]
C177  0.1uF  [c0402]
J13  JUMPER  [2_54MMTHROUGHHOLE]
R382  10K  [r0402]
R383  10K  [r0402]
R384  10K  [r0402]
R385  10K  [r0402]
R386  10K  [r0402]
R387  1K  [r0402]
RN10  R_Pak8  [EXB-2HVS]
RN11  R_Pak8  [EXB-2HVS]
U8  IS42S16400F-7BL  [54FBGA]
U47  SN74CBTLV3245ARGY  [RGY_QFN20]
sheet PAGE14: SENSOR, LED, PB
C84  0.1uF  [c0402]
C85  100pF  [c0603]
C86  0.1uF  [c0402]
C87  100pF  [c0603]
C88  0.1uF  [c0402]
D3  HET1_17  [d0603]
D4  HET1_31  [d0603]
D5  HET1_00  [d0603]
D6  HET1_25  [d0603]
D7  HET1_18  [d0603]
D8  HET1_29  [d0603]
J15  MicroSD Slot  [MicroSD]
LED1  HET1_27  [d0603]
LED2  HET1_05  [d0603]
R146  2.2K  [r0402]
R147  2.2K  [r0402]
R148  Thermal Resistor  [r0603]
R149  2.2K  [r0402]
R150  2.2K  [r0402]
R151  100K  [r0402]
R152  2.2K  [r0402]
R153  2.2K  [r0402]
R154  2.2K  [r0402]
R155  4.99k  [r0402]
R156  2.2K  [r0402]
R157  10K  [r0402]
R158  0  [r0402]
R256  0  [r0402]
S1  Push Button  [SW-SMT2]
U9  TEMT6000  [4mmL2mmW]
sheet PAGE22: DMM and RTP
J6  RTP-mictor  [SMC_MICTOR38]
J12  DMM-mictor  [SMC_MICTOR38]
sheet PAGE25: RESET
C141  1uF  [c0402]
C142  0.1uF  [c0402]
C143  0.1uF  [c0402]
C144  NO-POP  [c0402]
C145  0.1uF  [c0402]
C146  NO-POP  [c0402]
C147  1uF  [c0402]
R268  10k  [r0402]
R271  22  [r0402]
R273  10K  [r0402]
R274  10K  [r0402]
R275  10K  [r0402]
R276  2.2K  [r0402]
R279  0  [r0402]
R282  25.2K  [r0402]
R283  10k  [r0402]
R284  10k  [r0402]
R285  2.2K  [r0402]
R286  10k  [r0402]
R287  10k  [r0402]
R288  22  [r0402]
S3  WARM_RESET Button  [SW-SMT2]
S4  POR_RESET Button  [SW-SMT2]
U32  SN74LVC3G07  [VSSOP8]
U33  TPS3808G09DBVR  [SOT-23-6]
U34  TPS3808G09DBVR  [SOT-23-6]
sheet PAGE26: Power Supply
C148  10uF  [c1206_pol]
C149  0.1uF  [c0402]
C150  10uF  [c1206_pol]
C151  1uF  [c0603]
C152  10uF  [c1206_pol]
C154  10uF  [c1206_pol]
C155  10uF  [c1206_pol]
C156  2.2uF  [c0402]
DS2  1V2  [d0603]
DS3  5V  [d0603]
DS4  3V3  [d0603]
J8  JUMPER  [2_54MMTHROUGHHOLE]
Q1  FJV3109R  [sot23-28x44]
R290  1k  [r0402]
R291  0  [r0402]
R292  NOP  [r0402]
R293  NOP  [r0402]
R294  1K  [r0402]
R295  1K  [r0402]
R296  1.5K  [r0402]
R297  560  [r0402]
R299  113, 1%  [r1206]
R300  294, 1%  [r0603]
R301  340, 1%  [r0603]
U35  TPS73701DRB  [DRB_SON8]
U36  REG1117  [SOT-223]
sheet PAGE29: EXP P3
J11  EXP P3  [MMS_2mmx40]

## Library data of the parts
C1-C17 C19 C21-C26 C149 = Cap_0.1uF_Cermc_16V_10%_402: Manufacturer: Panasonic - ECG; Part Number: EMK105BJ104KV-F
C18 C20 C76-C82 C84 C86 C88 C143 C145 C177 = CAP_NP: Manufacturer: Panasonic - ECG; Part Number: EMK105BJ104KV-F
R1-R31 = 0ohm402_resistor_2
R32-R35 R52 R55-R60 R71 R72 R81-R84 R91 R92 R157 R273-R275 R382-R386 = R: Manufacturer: Panasonic - ECG; Part Number: ERJ-2GEJ103X
R36 R37 R39-R41 R43 R44 R47-R50 = R_0: Manufacturer: Panasonic - ECG; Part Number: ERJ-2GEJ220X
RN1-RN3 = R_Pak8: Manufacturer: Panasonic - ECG; Part Number: EXB-2HV220JV
R61 R78-R80 R93 R97 R349 = RESISTOR: Manufacturer: Panasonic - ECG; Part Number: ERJ-2GEJ220X
R87-R90 R94 R96 R98 R100 R102 R104 R106 R108 = RESISTOR: Manufacturer: Panasonic - ECG; Part Number: ERJ-2GE0R00X
U1 = TMS570LS30336U_BGA337_19: Manufacturer: TI; PACKAGE: 1; Part Number: TMS570LS3x
C75 C83 = CAP_NP: Manufacturer: Panasonic - ECG; Part Number: JMK107BJ106MA-T
J8 J13 = JUMPER: JUMPER PLUG 2POS SINGLE ROW, 2.54mm pitch; Part Number: XG8S-0231
R387 = R: Manufacturer: Panasonic - ECG; Part Number: ERJ-2GEJ102X
RN10 RN11 = RESISTOR_DIP_8_0: Manufacturer: Panasonic - ECG; Part Number: EXB-2HV220JV
U8 = IS42S16400F-7BL
U47 = SN74CBTLV3245ARGY
C85 C87 = Cap_100nF_Cermc_16V_10%_603: Manufacturer: Panasonic; Part Number: CC0603KRX7R7BB104
D3-D8 LED1 LED2 = LED_0: Manufacturer: Panasonic - SSG; Part Number: LNJ026X8BRA1
J15 = MicroSD_Slot_1: Manufacturer: Amphenol Commercial Products; Part Number: 101-00660-68-6; Vendor: Digikey; VendorNum: 101-00660-68-6-1-ND
R146 R147 R149 R150 R152-R154 R156 = R: Manufacturer: Panasonic - ECG; Part Number: ERJ-2RKF2201X; Vendor: Digikey; VendorNum: P2.20KLCT-ND
R148 = R: Manufacturer: Murata Electronics North America; Part Number: NCP18WF104J03RB
R151 = R: Manufacturer: Panasonic - ECG; Part Number: ERJ-2GEJ104X
R155 = R: Manufacturer: Panasonic - ECG; Part Number: ERJ-2RKF4991X
R158 R279 = R: Manufacturer: Panasonic - ECG; Part Number: ERJ-2GE0R00X
R256 = R: Part Number: ERJ-2GE0R00X
S1 S3 S4 = SW_PUSHBUTTON: Manufacturer: ALPS; Part Number: SKRKAHE010
U9 = TEMT6000: Manufacturer: Vishay/Semiconductors; Part Number: TEMT6000X01
J6 = RTP-mictor
J12 = DMM-mictor: Manufacturer: Tyco Electronics; Part Number: 2-5767004-2
C141 C147 = CAP_NP: Manufacturer: Panasonic - ECG; Part Number: ECJ-0EB1A105M
C142 = CAP_NP: Manufacturer: Panasonic - ECG; Part Number: ECJ-0EB1C104K
C144 C146 = CAP_NP_0
R268 R283 R284 R286 R287 = R: Manufactire: Panasonic - ECG; Part Number: ERJ-2GEJ103X
R271 R288 = R: Part Number: ERJ-2GEJ220X
R276 R285 = R: Manufactire: Panasonic - ECG; Part Number: ERJ-2RKF2201X
R282 = R_1: Part Number: ERJ-2RKF2552X
U32 = SN74LVC3G07: Manufacturer: TI; Part Number: SN74LVC3G07DCUR
U33 U34 = TPS3808G09DBVR: Manufacturer: TI
C148 C150 C152 C154 C155 = CAP_P: CAP TANT 10UF 10V 20% SMD; Manufacturer: Kemet; Part Number: T491A106M020AT
C151 = Cap_0.1uF_Cermc_16V_10%_402: Manufacturer: Panasonic - ECG; Part Number: JMK107BJ105KK-T
C156 = CAP_NP: Part Number: JMK105BJ225MV-F
DS2-DS4 = LED_0: Manufacturer: Panasonic - SSG; Part Number: LNJ926W8CRA
Q1 = 2N2222_0: Part Number: BC848ALT1G
R290 = RESISTOR: Manufacturer: Panasonic - ECG; Part Number: ERJ-2GEJ102X
R291 = RESISTOR: Manufacturer: Panasonic - ECG; Part Number: ERJ-2RKF2322X
R292 = RESISTOR
R293 = RESISTOR: Manufacturer: Panasonic - ECG; Part Number: ERJ-2RKF9532X
R294 = R_0: Manufacturer: Panasonic - ECG; Part Number: ERJ-2GEJ102X
R295 = R_0: Part Number: ERJ-2GEJ102X
R296 = R: Resistor, 5%, 1/10W; Manufacturer: Panasonic - ECG; Part Number: ERJ-2GEJ152X
R297 = R: Resistor, 5%, 1/10W; Part Number: ERJ-2GEJ561X
R299 = RESISTOR: Manufacturer: Panasonic - ECG; Part Number: ERJ-8ENF1130V
R300 = RESISTOR: Manufacturer: Yageo; Part Number: ERJ-3EKF2940V
R301 = RESISTOR: Manufacturer: Panasonic - ECG; Part Number: ERJ-3EKF3400V
U35 = TPS73701DRB: Part Number: TPS73701DRBR
U36 = REG1117
J11 = CONN_PLUG_40x2: Manufacturer: Samtec Inc; Part Number: MMS-140-01-T-DV

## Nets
GND: C1.2 C2.2 C3.2 C4.2 C5.2 C6.2 C7.2 C8.2 C9.2 C10.2 C11.2 C12.2 C13.2 C14.2 C15.2 C16.2 C17.2 C18.2 C19.2 C20.2 C21.2 C22.2 C23.2 C24.2 C25.2 C26.2 C75.2 C76.2 C77.2 C78.2 C79.2 C80.2 C81.2 C82.2 C83.2 C84.2 C85.2 C86.2 C87.2 C88.2 C141.1 C142.1 C143.2 C144.2 C145.2 C146.2 C147.1 C148.2(CATHODE) C150.2(CATHODE) C151.1 C152.2(CATHODE) C154.2(CATHODE) C155.2(CATHODE) C156.1 C177.2 D3.2(CATHODE) D4.2(CATHODE) D5.2(CATHODE) D6.2(CATHODE) D7.2(CATHODE) D8.2(CATHODE) DS3.2(CATHODE) DS4.2(CATHODE) J6.29(GND) J6.30(GND) J6.39(GND) J6.40(GND) J6.41(GND) J6.42(GND) J6.43(GND) J11.2 J11.4 J11.35 J11.36 J11.69 J11.80 J12.37(future7) J12.38(future6) J12.39(GND) J12.40(GND) J12.41(GND) J12.42(GND) J12.43(GND) J15.6(VSS) LED1.2(CATHODE) LED2.2(CATHODE) Q1.2(EMITTER) R30.1 R31.2 R151.2 R155.2 R256.2 R283.1 R286.1 R292.2 R293.2 R300.2 R301.2 R385.1 R386.1 S1.2 S3.1 S4.1 U8.A1(VSS.1) U8.A3(VSSQ.1) U8.B7(VSSQ.2) U8.C3(VSSQ.3) U8.D7(VSSQ.4) U8.E3(VSS.2) U8.J1(VSS.3) U32.4(GND) U33.2(GND) U34.2(GND) U35.4(GND) U35.9(PAD) U47.10(GND) U47.21(PAD) ; also on sheet 13 14 15 16 17 18 19 22 23 24 25 27 28 29
VCC_1V2: C149.2 C150.1(ANODE) C151.2 R285.2 R291.1 R295.1 U35.1(OUT) ; also on sheet 16
VCC_3V3: C75.1 C76.1 C77.1 C78.1 C79.1 C80.1 C81.1 C82.1 C83.1 C84.1 C86.1 C88.1 C142.2 C143.1 C145.1 C148.1(ANODE) C177.1 J15.4(VDD) R32.2 R33.2 R34.2 R35.2 R52.2 R55.2 R56.2 R57.2 R58.2 R59.2 R60.2 R71.2 R72.2 R81.2 R82.2 R83.2 R84.2 R91.2 R92.2 R148.1 R157.1 R268.2 R273.2 R274.2 R275.2 R276.2 R282.1 R284.2 R287.2 R290.1 R297.1 R382.2 R383.2 R384.2 R387.1 U8.A7(VDDQ.1) U8.A9(VDD.1) U8.B3(VDDQ.2) U8.C7(VDDQ.3) U8.D3(VDDQ.4) U8.E7(VDD.2) U8.J9(VDD.3) U9.3(C) U32.8(VCC) U33.6(VDD) U34.6(VDD) U35.8(IN) U47.20(VCC) ; also on sheet 13 14 15 16 17 18 19 21 25 27 28 29
VCC_5V: R294.2 R296.1 ; also on sheet 13 17 19 24 27
VCC_12V: C152.1(ANODE) U36.3(IN) ; also on sheet 13
VCC_ADC: C154.1(ANODE) C156.2 R22.2 R23.1 R299.1 U36.2(OUT) U36.4(TAB_OUT) ; also on sheet 16
AD1IN0: R2.1 ; also on sheet 22
AD1IN1: R4.1 ; also on sheet 22
AD1IN2: R1.1 ; also on sheet 22
AD1IN3: R7.1 ; also on sheet 22
AD1IN4: R9.1 ; also on sheet 22
AD1IN5: R11.1 ; also on sheet 22
AD1IN6: R13.1 ; also on sheet 22
AD1IN7: R15.1 ; also on sheet 22
AD1IN8: C85.1 R17.1 R148.2 R151.1 ; also on sheet 22
AD1IN9: C87.1 R18.1 R155.1 U9.1(E) ; also on sheet 22
AD1IN10: R20.1 ; also on sheet 22
AD1IN11: R21.1 ; also on sheet 22
AD1IN12: R24.1 ; also on sheet 22
AD1IN13: R25.1 ; also on sheet 22
AD1IN14: R27.1 ; also on sheet 22
AD1IN15: R28.1 ; also on sheet 22
AD2IN0: R3.2 ; also on sheet 22
AD2IN1: R5.2 ; also on sheet 22
AD2IN2: R6.2 ; also on sheet 22
AD2IN3: R8.2 ; also on sheet 22
AD2IN4: R10.2 ; also on sheet 22
AD2IN5: R12.2 ; also on sheet 22
AD2IN6: R14.2 ; also on sheet 22
AD2IN7: R16.2 ; also on sheet 22
ADREFHI: R26.2 ; also on sheet 22
ADREFLO: R29.2 ; also on sheet 22
ARM_JTAG_RESETn: R274.1 U32.1(1A) ; also on sheet 18
CAN1_RX: J11.7 ; also on sheet 19 26
CAN1_TX: J11.8 ; also on sheet 19 26
CAN2_RX: J11.9 ; also on sheet 19 26
CAN2_TX: J11.10 ; also on sheet 19 26
CAN3_RX: J11.11 ; also on sheet 26
CAN3_TX: J11.12 ; also on sheet 26
DMMCLK: J12.5(DMMCLK2) J12.6(DMMCLK1) R78.2
DMMDATA0: J12.11(DMMDATA0) U1.L19(DMM_DATA0)
DMMDATA1: J12.12(DMMDATA1) U1.L18(DMM_DATA1)
DMMDATA2: J12.13(DMMDATA2) R72.1 U1.W6(MIBSPI5NCS[2]/DMM_DATA[2]) ; also on sheet 22
DMMDATA3: J12.14(DMMDATA3) R71.1 U1.T12(MIBSPI5NCS[3]/DMM_DATA[3]) ; also on sheet 22
DMMDATA4: J12.15(DMMDATA4) R87.1 U1.H19(MIBSPI5CLK/DMM_DATA[4]/MII_TXEN/RMII_TXEN)
DMMDATA5: J12.16(DMMDATA5) R88.1 U1.E19(MIBSPI5NCS[0]/DMM_DATA[5])
DMMDATA6: J12.17(DMMDATA6) R89.1 U1.B6(MIBSPI5NCS[1]/DMM_DATA[6])
DMMDATA7: J12.18(DMMDATA7) ; also on sheet 24
DMMDATA8: J12.19(DMMDATA8) R94.1 U1.J19(MIBSPI5SIMO[0]/DMM_DATA[8]/MII_TXD[1]/RMII_TXD[1])
DMMDATA9: J12.20(DMMDATA9) R96.1 U1.E16(MIBSPI5SIMO[1]/DMM_DATA[9])
DMMDATA10: J12.21(DMMDATA10) R98.1 U1.H17(MIBSPI5SIMO[2]/DMM_DATA[10])
DMMDATA11: J12.22(DMMDATA11) R100.1 U1.G17(MIBSPI5SIMO[3]/DMM_DATA[11])
DMMDATA12: J12.23(DMMDATA12) R102.1 U1.J18(MIBSPI5SOMI[0]/DMM_DATA[12]/MII_TXD[0]/RMII_TXD[0])
DMMDATA13: J12.24(DMMDATA13) R104.1 U1.E17(MIBSPI5SOMI[1]/DMM_DATA[13])
DMMDATA14: J12.25(DMMDATA14) R106.1 U1.H16(MIBSPI5SOMI[2]/DMM_DATA[14])
DMMDATA15: J12.26(DMMDATA15) R108.1 U1.G16(MIBSPI5SOMI[3]/DMM_DATA[15])
DMMENAn: J12.10(DMMENAn) R79.2
DMMSYNC: J12.8(DMMSYNC) R80.2
EMIF_CKE: R43.1 U47.4(A3)
EMIF_CLK: R41.1 U8.F2(CLK)
EMIF_nCAS: R39.1 U8.F7(~{CAS})
EMIF_nRAS: R37.1 U8.F8(~{RAS})
EMIFA0_NHET201: RN1.3 U8.H7(A0) ; also on sheet 22
EMIFA1_NHET203: RN1.4 U8.H8(A1) ; also on sheet 22
EMIFA2_ETMD11: RN1.5 U8.J8(A2) ; also on sheet 18 22
EMIFA2_ETMD11B: RN1.12 ; also on sheet 21
EMIFA3_ETMD10: RN1.6 U8.J7(A3) ; also on sheet 18 22
EMIFA3_ETMD10B: RN1.11 ; also on sheet 21
EMIFA4_ETMD9: RN1.7 U8.J3(A4) ; also on sheet 18 22
EMIFA4_ETMD9B: RN1.10 ; also on sheet 21
EMIFA5_ETMD8: RN1.8 U8.J2(A5) ; also on sheet 18 22
EMIFA5_ETMD8B: RN1.9 ; also on sheet 21
EMIFA6_RTPD13: J6.24(RTPDATA13) RN2.1 U8.H3(A6) ; also on sheet 22
EMIFA7_RTPD12: J6.23(RTPDATA12) RN2.2 U8.H2(A7) ; also on sheet 22
EMIFA8_RTPD11: J6.22(RTPDATA11) RN2.3 U8.H1(A8) ; also on sheet 22
EMIFA9_RTPD10: J6.21(RTPDATA10) RN2.4 U8.G3(A9) ; also on sheet 22
EMIFA10_RTPD9: J6.20(RTPDATA9) RN2.5 U8.H9(A10) ; also on sheet 22
EMIFA11_RTPD8: J6.19(RTPDATA8) RN2.6 U8.G2(A11) ; also on sheet 22
EMIFA12_RTPD6: J6.17(RTPDATA6) RN2.7 U8.G1(A12) ; also on sheet 22
EMIFA13_RTPD5: J6.16(RTPDATA5) RN2.8 ; also on sheet 22
EMIFA14_RTPD4: J6.15(RTPDATA4) RN3.1 ; also on sheet 22
EMIFA15_RTPD3: J6.14(RTPDATA3) RN3.2 ; also on sheet 22
EMIFA16_RTPD2: J6.13(RTPDATA2) RN3.3 ; also on sheet 22
EMIFA17_RTPD1: J6.12(RTPDATA1) RN3.4 ; also on sheet 22
EMIFA18_RTPD0: J6.11(RTPDATA0) RN3.5 ; also on sheet 22
EMIFA19_RTPNENA: J6.10(nRTPENA) RN3.6 ; also on sheet 22
EMIFA20_RTPNSYNC: J6.8(RTPSYNC) RN3.7 ; also on sheet 22
EMIFA21_RTPCLK: J6.5(RTPCLK2) J6.6(RTPCLK1) RN3.8 ; also on sheet 22
EMIFBA0_ETMD12: U8.G7(BA0) ; also on sheet 18 21 22
EMIFBA1_NHET205: R40.1 R52.1 U8.G8(BA1) ; also on sheet 22
EMIFD0_ETMD16: RN11.16 ; also on sheet 18 21 22
EMIFD1_ETMD17: RN11.15 ; also on sheet 18 21 22
EMIFD2_ETMD18: RN11.14 ; also on sheet 18 21 22
EMIFD3_ETMD19: RN11.13 ; also on sheet 18 21 22
EMIFD4_ETMD20: RN11.12 ; also on sheet 18 21 22
EMIFD5_ETMD21: RN11.11 ; also on sheet 18 21 22
EMIFD6_ETMD22: RN11.10 ; also on sheet 18 21 22
EMIFD7_ETMD23: RN11.9 ; also on sheet 18 21 22
EMIFD8_ETMD24: RN10.9 ; also on sheet 18 21 22
EMIFD9_ETMD25: RN10.10 ; also on sheet 18 21 22
EMIFD10_ETMD26: RN10.11 ; also on sheet 18 21 22
EMIFD11_ETMD27: RN10.12 ; also on sheet 18 21 22
EMIFD12_ETMD28: RN10.13 ; also on sheet 18 21 22
EMIFD13_ETMD29: RN10.14 ; also on sheet 18 21 22
EMIFD14_ETMD30: RN10.15 ; also on sheet 18 21 22
EMIFD15_ETMD31: RN10.16 ; also on sheet 18 21 22
EMIFNCS0_RTPD15: J6.26(RTPDATA15) R47.1 U47.5(A4)
EMIFNCS2: R35.1 R50.1 ; also on sheet 22
EMIFNCS3_RTPD14: J6.25(RTPDATA14) R34.1 R49.1 ; also on sheet 22
EMIFNCS4_RTPD7: J6.18(RTPDATA7) R33.1 R48.1 ; also on sheet 22
EMIFNDQM0_ETMD15: U47.3(A2) ; also on sheet 18 21 22
EMIFNDQM1_ETMD14: U47.2(A1) ; also on sheet 18 21 22
EMIFNWE_EMIFNWR: R44.1 U8.F9(~{WE}) ; also on sheet 22
ETH_RESETn: C141.2 R268.1 R271.2 U32.2(3Y) U32.5(2Y) U32.7(1Y) ; also on sheet 14 15 22 28
EXP_12V: J11.1 J11.3 J11.79 ; also on sheet 13 22
EXP_EMIF_nWAIT: R32.1 R36.1 ; also on sheet 22
FLEXRAY_RX1: J11.13 ; also on sheet 26
FLEXRAY_RX2: J11.14 ; also on sheet 26
FLEXRAY_TX1: J11.15 ; also on sheet 26
FLEXRAY_TX2: J11.16 ; also on sheet 26
FLEXRAY_TXEN1: J11.17 ; also on sheet 26
FLEXRAY_TXEN2: J11.18 ; also on sheet 26
GIOA0: J11.20 ; also on sheet 25
GIOA0_W2FCRXDPI: U1.A5(GIOA[0]/OHCI_PRT_RcvDpls[1]/W2FC_RXDPI) ; also on sheet 25
GIOA1: J11.19 ; also on sheet 25
GIOA1_W2FCRXDMI: U1.C2(GIOA[1]/OHCI_PRT_RcvDmns[1]/W2FC_RXDMI) ; also on sheet 25
GIOA2: J11.22 ; also on sheet 25
GIOA2_W2FCTXDO: U1.C1(GIOA[2]/OHCI_RCFG_txdPls[1]/W2FC_TXDO/NHET2[0]) ; also on sheet 25
GIOA3: J11.21 U1.E1(GIOA[3]/NHET2[2])
GIOA4: J11.24 U1.A6(GIOA[4])
GIOA5: J11.23 U1.B5(GIOA[5]/EXTCLKIN)
GIOA6: J11.26 U1.H3(GIOA[6]/NHET2[4])
GIOA7: J11.25 R158.1 U1.M1(GIOA[7]/NHET2[6])
GIOB0: J11.28 ; also on sheet 24
GIOB0_OHCItxDpls0: U1.M2(GIOB[0]/OHCI_RCFG_txDpls[0]) ; also on sheet 24
GIOB1: J11.27 ; also on sheet 24
GIOB1_OHCIPrtPower0: U1.K2(GIOB[1]/OHCI_RCFG_PrtPower[0]) ; also on sheet 24
GIOB2: J11.30 U1.F2(GIOB2)
GIOB3: J11.29 ; also on sheet 25
GIOB3_W2FCRXDI: U1.W10(GIOB[3]/OHCI_PRT_RcvData[1]/W2FC_RXDI) ; also on sheet 25
GIOB4: J11.32 U1.G1(GIOB4)
GIOB5: J11.31 U1.G2(GIOB5)
GIOB6: J11.34 U1.J2(GIOB6)
GIOB7: J11.33 U1.F1(GIOB7)
LIN_RX: J11.5 ; also on sheet 26
LIN_TX: J11.6 ; also on sheet 26
MIPI_JTAG_RESETn: R273.1 U32.3(2A) ; also on sheet 18
NHET100: J11.38 R149.1 U1.K18(NHET1[00]/SPI2CLK)
NHET101: J11.37 ; also on sheet 25
NHET101_W2FCPUENO: U1.V2(NHET1[01]/SPI4ENA/OHCI_RCFG_txEnL[1]/W2FC_PUENO/NHET2[8]) ; also on sheet 25
NHET102: J11.40 U1.W5(NHET1[02]/SPI4SIMO)
NHET103: J11.39 ; also on sheet 25
NHET103_W2FCPUENON: U1.U1(NHET1[03]/SPI4NCS[0]/OHCI_RCFG_speed[1]/W2FC_PUENON/NHET2[10]) ; also on sheet 25
NHET104: J11.42 U1.B12(NHET1[04])
NHET105: J11.41 R156.1 U1.V6(NHET1[05]/SPI4SOMI/NHET2[12])
NHET106_SCIRX: J11.44 U1.W3(NHET1[06]/SCIRX)
NHET107: J11.43 ; also on sheet 25
NHET107_W2FCGZO: U1.T1(NHET1[07]/OHCI_RCFG_PrtPower[1]/W2FC_GZO/NHET2[14]) ; also on sheet 25
NHET108: J11.46 ; also on sheet 24
NHET108_OHCIOvrCurrent0: U1.E18(NHET1[08]/MIBSPI1SIMO[1]/MII_TXD[3]/OHCI_PRT_OvrCurrent[0]) ; also on sheet 24
NHET109: J11.45 ; also on sheet 25
NHET109_W2FCSUSPENDO: U1.V7(NHET1[09]/NHET2[16]/OHCI_RCFG_suspend[1]/W2FC_SUSPENDO) ; also on sheet 25
NHET110: J11.48 ; also on sheet 24
NHET110_OHCITxEnL0: U1.D19(NHET1[10]/MII_TX_CLK/OHCI_RCFG_txEnL[0]/MII_TX_AVCLK4) ; also on sheet 24
NHET111: J11.47 ; also on sheet 25
NHET111_W2FCVBUSI: U1.E3(NHET1[11]/MIBSPI3NCS[4]/NHET2[18]/OHCI_PRT_OvrCurrent[1]/W2FC_VBUSI) ; also on sheet 25
NHET112: J11.50 ; also on sheet 29
NHET112_RMIICRSDV: U1.B4(NHET1[12]/MII_CRS/RMII_CRS_DV) ; also on sheet 29
NHET113_SCITX: J11.49 U1.N2(NHET1[13]/SCITX)
NHET114: J11.52 ; also on sheet 24
NHET114_OHCITxSe00: U1.A11(NHET1[14]/OHCI_RCFG_txSe0[0]) ; also on sheet 24
NHET115_SPI1CS4: J11.51 U1.N1(NHET1[15]/MIBSPI1NCS[4])
NHET116: J11.54 U1.A4(NHET1[16])
NHET117: J11.53 R146.1 U1.A13(NHET1[17])
NHET118: J11.56 R152.1 U1.J1(NHET1[18])
NHET119: J11.55 U1.B13(NHET1[19])
NHET120: J11.58 U1.P2(NHET1[20])
NHET121: J11.57 U1.H4(NHET1[21])
NHET122: J11.60 ; also on sheet 25
NHET122_W2FCSE0O: U1.B3(NHET1[22]/OHCI_RCFG_txSe0[1]/W2FC_SE0O) ; also on sheet 25
NHET123: J11.59 U1.J4(NHET1[23])
NHET124: J11.62 ; also on sheet 29
NHET124_RMIIRXD0: U1.P1(NHET1[24]/MIBSPI1NCS[5]/MII_RXD[0]/RMII_RXD[0]) ; also on sheet 29
NHET125: J11.61 R150.1 U1.M3(NHET1[25])
NHET126: J11.64 ; also on sheet 29
NHET126_RMIIRXD1: U1.A14(NHET1[26]/MII_RXD[1]/RMII_RXD[1]) ; also on sheet 29
NHET127: J11.63 R154.1 U1.A9(NHET1[27])
NHET128: J11.66 ; also on sheet 29
NHET128_RMIIREFCLK: U1.K19(NHET1[28]/MII_RXCLK/RMII_REFCLK/MII_RX_AVCLK4) ; also on sheet 29
NHET129: J11.65 R153.1 U1.A3(NHET1[29])
NHET130: J11.68 ; also on sheet 24
NHET130_OHCISPEED0: U1.B11(NHET1[30]/MII_RX_DV/OHCI_RCFG_speed[0]) ; also on sheet 24
NHET131: J11.67 R147.1 U1.J17(NHET1[31])
POR_RESETn: R279.1 ; also on sheet 14 22
RMII_RXER_AD1EVT: R19.2 ; also on sheet 29
RSTn: J11.70 ; also on sheet 14
RTP_JTAG_RESETn: J6.34(nRST) R275.1 U32.6(3A)
RTP_RTCK: J6.32(RTCK) ; also on sheet 18
RTP_TCK: J6.31(TCK) ; also on sheet 18
RTP_TDI: J6.35(TDI) ; also on sheet 18
RTP_TDO: J6.36(TDO) ; also on sheet 18
RTP_TMS: J6.37(TMS) ; also on sheet 18
RTP_TRSTn: J6.33(nTRST) ; also on sheet 18
SPI1_CLK: R61.1 ; also on sheet 22
SPI1CS0_OHCIRCVDATA0: R55.1 U1.R2(MIBSPI1NCS[0]/MIBSPI1SOMI[1]/MII_TXD[2]/OHCI_PRT_RcvData[0]) ; also on sheet 24
SPI1CS1_NHET117_OHCISUSPEN0: R56.1 U1.F3(MIBSPI1NCS[1]/NHET1[17]/MII_COL/OHCI_RCFG_suspend[0]) ; also on sheet 24
SPI1CS2_NHET119_MDIO: R57.1 U1.G3(MIBSPI1NCS[2]/NHET1[19]/MDIO) ; also on sheet 29
SPI1CS3_NHET121: R58.1 U1.J3(MIBSPI1NCS[3]/NHET1[21]) ; also on sheet 22
SPI1ENA_NHET123_OHCIRCVDPLS0: U1.G19(MIBSPI1NENA/NHET1[23]/MII_RXD[2]/OHCI_PRT_RcvDpls[0]) ; also on sheet 24
SPI1SIMO: U1.F19(MIBSPI1SIMO) ; also on sheet 22
SPI1SOMI: U1.G18(MIBSPI1SOMI) ; also on sheet 22
SPI2CLK: J15.5(CLK) R349.2 ; also on sheet 22
SPI2CS0: J15.2(D3-CD) R59.1 U1.N3(SPI2NCS[0]) ; also on sheet 22
SPI2ENA: J15.12(CD) R60.1 U1.D3(SPI2NENA/SPI2CS[1]) ; also on sheet 22
SPI2SIMO: J15.3(CMD-MOSI) U1.D1(SPI2SIMO) ; also on sheet 22
SPI2SOMI: J15.7(D0-MISO) U1.D2(SPI2SOMI) ; also on sheet 22
SPI3CLK: J11.78 R93.1
SPI3CS0_AD2EVT_GIOB2: J11.76 R81.1 U1.V10(MIBSPI3NCS[0]/AD2EVT/GIOB[2]) ; also on sheet 22
SPI3CS1_NHET125: J11.75 ; also on sheet 29
SPI3CS1_NHET125_MDCLK: R82.1 R97.1 ; also on sheet 29
SPI3CS2_I2CSDA_NHET127: J11.72 R83.1 U1.B2(MIBSPI3NCS[2]/I2C_SDA/NHET1[27])
SPI3CS3_I2CSCL_NHET129: J11.71 R84.1 U1.C3(MIBSPI3NCS[3]/I2C_SCL/NHET1[29])
SPI3ENA_NHET131: J11.77 U1.W9(MIBSPI3NENA/MIBSPI3NCS[5]/NHET1[31])
SPI3SIMO: J11.73 U1.W8(MIBSPI3SIMO)
SPI3SOMI: J11.74 U1.V8(MIBSPI3SOMI)
SPI5CLK_RMIITXEN: R87.2 ; also on sheet 29
SPI5CS0n: R88.2 R92.1 ; also on sheet 22
SPI5CS1n: R89.2 R91.1 ; also on sheet 22
SPI5EN_OHCIRCVDMNS0: R90.2 ; also on sheet 24
SPI5SIMO0_RMIITXD1: R94.2 ; also on sheet 29
SPI5SIMO1: R96.2 ; also on sheet 22
SPI5SIMO2: R98.2 ; also on sheet 22
SPI5SIMO3: R100.2 ; also on sheet 22
SPI5SOMI0_RMIITXD0: R102.2 ; also on sheet 29
SPI5SOMI1: R104.2 ; also on sheet 22
SPI5SOMI2: R106.2 ; also on sheet 22
SPI5SOMI3: R108.2 ; also on sheet 22
N16373453: C20.1 R23.2 R29.1 R31.1 U1.V16(VREFLO)
N16405285: RN10.1 U8.A2(DQ15)
N16405343: RN10.2 U8.B1(DQ14)
N16405353: RN11.7 U8.D8(DQ6)
N16405357: RN10.7 U8.D2(DQ9)
N16405361: RN11.5 U8.C8(DQ4)
N16405365: RN11.1 U8.A8(DQ0)
N16405369: RN10.4 U8.C1(DQ12)
N16405373: RN10.6 U8.D1(DQ10)
N16405377: RN11.8 U8.E9(DQ7)
N16405381: RN10.5 U8.C2(DQ11)
N16405385: RN10.3 U8.B2(DQ13)
N16405389: RN11.2 U8.B9(DQ1)
N16405393: RN10.8 U8.E1(DQ8)
N16405397: RN11.3 U8.B8(DQ2)
N16405401: RN11.6 U8.D9(DQ5)
N16405405: RN11.4 U8.C9(DQ3)
N16436940: R276.1 R279.2 U33.1(~{RESE}T)
N16436978: R284.1 U33.3(~{MR}) U34.1(~{RESE}T)
N16437014: R282.2 R283.2 U33.5(SENSE1)
N16437022: C147.2 R287.1 R288.2 U34.3(~{MR})
N16437062: C146.1 U34.4(CT)
N16437066: R285.1 R286.2 U34.5(SENSE1)
N16437136: R288.1 S4.2
N16437164: C144.1 U33.4(CT)
N16456844: R157.2 R158.2 S1.1
N16699130: R44.2 U1.D17(EMIF_nWE/EMIF_nWR)
N16699226: R47.2 U1.N17(EMIF_nCS[0]/RTP_DATA[15]/NHET2[7])
N16699378: R48.2 U1.M17(EMIF_nCS[4]/RTP_DATA[07])
N16699382: R49.2 U1.K17(EMIF_nCS[3]/RTP_DATA[14]/NHET2[9])
N16699386: R50.2 U1.L17(EMIF_nCS[2])
N16699390: R43.2 U1.L3(EMIF_CKE)
N16699394: R41.2 U1.K3(EMIF_CLK)
N16699398: R36.2 U1.P3(EMIF_nWAIT)
N16699402: R37.2 U1.R3(EMIF_nRAS)
N16699406: R39.2 U1.R4(EMIF_nCAS)
N16832513: C18.1 R22.1 R26.1 R30.2 U1.V15(VREFHI)
N16841100: C15.1 R3.1 U1.V13(AD1IN16/AD2IN0)
N16841127: C13.1 R5.1 U1.U13(AD1IN17/AD2IN1)
N16841130: C11.1 R6.1 U1.U14(AD1IN18/AD2IN2)
N16841133: C9.1 R8.1 U1.U16(AD1IN19/AD2IN3)
N16841136: C7.1 R10.1 U1.U15(AD1IN20/AD2IN4)
N16841139: C5.1 R12.1 U1.T15(AD1IN21/AD2IN5)
N16841142: C3.1 R14.1 U1.R19(AD1IN22/AD2IN6)
N16841145: C1.1 R16.1 U1.R16(AD1IN23/AD2IN7)
N16884577: C12.1 R1.2 U1.V18(AD1IN2)
N16884586: C10.1 R7.2 U1.T17(AD1IN3)
N16884595: C8.1 R9.2 U1.U18(AD1IN4)
N16884604: C6.1 R11.2 U1.R17(AD1IN5)
N16884613: C4.1 R13.2 U1.T19(AD1IN6)
N16884622: C2.1 R15.2 U1.V14(AD1IN7)
N16884888: C17.1 R28.2 U1.P19(AD1IN15/AD2IN15)
N16884897: C19.1 R27.2 U1.R18(AD1IN14/AD2IN14)
N16884906: C21.1 R25.2 U1.T18(AD1IN13/AD2IN13)
N16884915: C22.1 R24.2 U1.T16(AD1IN12/AD2IN12)
N16884924: C23.1 R21.2 U1.U19(AD1IN11/AD2IN11)
N16884933: C24.1 R20.2 U1.U17(AD1IN10/AD2IN10)
N16884942: C25.1 R18.2 U1.W17(AD1IN9/AD2IN9)
N16884951: C26.1 R17.2 U1.P18(AD1IN8/AD2IN8)
N17011671: R290.2 R292.1 U35.5(EN)
N17011828: C149.1 R291.2 R293.1 U35.3(NR/FB)
N17067069: R90.1 U1.H18(MIBSPI5NENA/DMM_DATA[7]/MII_RXD[3]/OHCI_PRT_RcvDmns[0])
N17226985: D8.1(ANODE) R153.2
N17226988: D7.1(ANODE) R152.2
N17226997: D6.1(ANODE) R150.2
N17227000: D5.1(ANODE) R149.2
N17227003: D4.1(ANODE) R147.2
N17227006: D3.1(ANODE) R146.2
N17410204: J8.1 R300.1
N17411355: DS3.1(ANODE) R296.2
N17411369: DS4.1(ANODE) R297.2
N17411389: Q1.1(BASE) R295.2
N17558031: R19.1 U1.N19(AD1EVT/MII_RX_ER/RMII_RX_ER)
N17792391: C14.1 R4.2 U1.V17(AD1IN1)
N17792394: C16.1 R2.2 U1.W14(AD1IN0)
N17792961: R40.2 U1.D16(EMIF_BA[1]/NHET2[5])
N17793935: R61.2 U1.F18(MIBSPI1CLK)
N17794103: R93.2 U1.V9(MIBSPI3CLK)
N17794109: R97.2 U1.V5(MIBSPI3NCS[1]/NHET1[25]/MDCLK)
N17794209: R78.1 U1.F17(DMM_CLK)
N17794212: R79.1 U1.F16(DMM_nENA)
N17794215: R80.1 U1.J16(DMM_SYNC)
N17838507: C155.1(ANODE) J8.2 R299.2 R301.1 U36.1(ADJ/GND)
N17906848: R271.1 S3.2
N18057639: RN1.14 U1.D4(EMIF_ADDR[0]/NHET2[1])
N18057640: RN1.13 U1.D5(EMIF_ADDR[1]/NHET2[3])
N18057645: RN2.16 U1.C4(EMIF_ADDR[6]/RTP_DATA[13]/NHET2[11])
N18057646: RN2.15 U1.C5(EMIF_ADDR[7]/RTP_DATA[12]/NHET2[13])
N18057647: RN2.14 U1.C6(EMIF_ADDR[8]/RTP_DATA[11]/NHET2[15])
N18057648: RN2.13 U1.C7(EMIF_ADDR[9]/RTP_DATA[10])
N18057649: RN2.12 U1.C8(EMIF_ADDR[10]/RTP_DATA[09])
N18057650: RN2.11 U1.C9(EMIF_ADDR[11]/RTP_DATA[08])
N18057651: RN2.10 U1.C10(EMIF_ADDR[12]/RTP_DATA[06])
N18057652: RN2.9 U1.C11(EMIF_ADDR[13]/RTP_DATA[05])
N18057653: RN3.16 U1.C12(EMIF_ADDR[14]/RTP_DATA[04])
N18057654: RN3.15 U1.C13(EMIF_ADDR[15]/RTP_DATA[03])
N18057655: RN3.14 U1.D14(EMIF_ADDR[16]/RTP_DATA[02])
N18057656: RN3.13 U1.C14(EMIF_ADDR[17]/RTP_DATA[01])
N18057657: RN3.12 U1.D15(EMIF_ADDR[18]/RTP_DATA[0])
N18057658: RN3.11 U1.C15(EMIF_ADDR[19]/RTP_nENA)
N18057659: RN3.10 U1.C16(EMIF_ADDR[20]/RTP_nSYNC)
N18057660: RN3.9 U1.C17(EMIF_ADDR[21]/RTP_CLK)
N18276993: J15.9(SHIELD1) J15.10(SHIELD2) J15.11(SHIELD3) R256.1
N18278163: R349.1 U1.E2(SPI2CLK)
N18421375: R384.1 U8.F1(DQMH) U47.18(B1)
N18421378: R383.1 U8.E8(DQML) U47.17(B2)
N18421381: R385.2 U8.F3(CKE) U47.16(B3)
N18421390: R382.1 U8.G9(~{CS}) U47.15(B4)
N18433413: J13.2 R386.2 U47.19(OEn)
N18433458: J13.1 R387.2
N18543073: DS2.1(ANODE) R294.1
N18543076: DS2.2(CATHODE) Q1.3(COLLECTOR)
N18674101: LED1.1(ANODE) R154.2
N18674204: LED2.1(ANODE) R156.2

Not connected (* = marked no-connect by the designer): J6 1(Not_use9)* 2(Not_use1)* 3(Not_use8)* 4(Not_use2)* 7(Not_use7)* 9(Not_use6)* 27(Not_use5) 28(Not_use3)* 38(Not_use4)*; J12 1(NC3)* 2(NC1)* 3(NC4)* 4(NC2)* 7(future14)* 9(future13)* 27(future12)* 28(future1)* 29(future11)* 30(future2)* 31(future10)* 32(future3)* 33(future9)* 34(future4)* 35(future8)* 36(future5)*; J15 1(D2-NC)* 8(D1-NC)*; RN1 1* 2* 15* 16*; U1 D6(ETMDATA[11]/EMIF_ADDR[2]) D7(ETMDATA[10]/EMIF_ADDR[3]) D8(ETMDATA[09]/EMIF_ADDR[4]) D9(ETMDATA[08]/EMIF_ADDR[5]) D10(ETMDATA[15]/EMIF_nDQM[0]) D11(ETMDATA[14]/EMIF_nDQM[1]) D12(ETMDATA[13]/EMIF_nOE) D13(ETMDATA[12]/EMIF_BA[0]) E4(ETMDATA[20]/EMIF_DATA[4]) F4(ETMDATA[21]/EMIF_DATA[5]) G4(ETMDATA[22]/EMIF_DATA[6]) K4(ETMDATA[23]/EMIF_DATA[7]) K16(ETMDATA[16]/EMIF_DATA[0]) L4(ETMDATA[24]/EMIF_DATA[8]) L16(ETMDATA[17]/EMIF_DATA[1]) M4(ETMDATA[25]/EMIF_DATA[9]) M16(ETMDATA[18]/EMIF_DATA[2]) N4(ETMDATA[26]/EMIF_DATA[10]) N16(ETMDATA[19]/EMIF_DATA[3]) P4(ETMDATA[27]/EMIF_DATA[11]) T5(ETMDATA[28]/EMIF_DATA[12]) T6(ETMDATA[29]/EMIF_DATA[13]) T7(ETMDATA[30]/EMIF_DATA[14]) T8(ETMDATA[31]/EMIF_DATA[15]) W13(RESERVED_AD2EVT)*; U8 E2(NC)*; U9 2(NC)*; U35 2(NC1)* 6(NC2)* 7(NC3)*; U47 1(NC)* 6(A5) 7(A6) 8(A7) 9(A8) 11(B8) 12(B7) 13(B6) 14(B5)

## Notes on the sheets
sheet 4
- NOTES, UNLESS OTHERWISE SPECIFIED:
- SCHEMATIC CONTENTS
- 1.  RESISTANCE VALUES IN OHMS.
- 2.  CAPACTITANCE VALUES IN MICROFARADS.
- 01 TITLE SHEET
  02 MCU ADC
  03 MCU EMIF
  04 MCU SPI
  05 MCU ETM
  06 MCU DCAN, FLEXRAY, and LIN
  07 MCU JTAG and OSC
  08 MCU NHET
  09 MCU GPIO
  10 MCU Power & GND
  11 FETSwitches for 1st USB
  12 EMIF Addr/ETM/RTP
  13 SDRAM
  14 Sensors, LEDs, and Pushbutton
  15 FET Switches for 2nd USB
  16 USB 1st OHCI Host
  17 USB device and 2nd OHCI Host
  18 FET Switch for RMII and DIP Switch
  19 Ethernet PHY & Connector
  20 CAN Transceivers
  21 JTAG and MIPI ETM Connector
  22 DMM and RTP Mictor Connectors
  23 XD100V2 FTDI2232
  24 XDS100V2 CPLD
  25 RESET
  26 Power Supply
  27 Power Inut
  28 EXP P1 and EXP P2
  29 EXP P3
- 3.  REFERENCE DESIGNATORS USED:
- 4.  ALL 0.1 uF AND 0.01uF CAPACITORS ARE DECOUPLING CAPS UNLESS
  OTHERWISE NOTED.  THEY ARE SHOWN ON THE PAGE WITH THE INTEGRATED
  CIRCUITS THEY SHOULD BE PLACED NEAR.
- 5.  NHET1xx means NHET1_[xx].
- 6.  OBSERVE THE LAYOUT NOTES IN SCHEMATIC.
- Changes on RevC:
- 1. Changed SD card slot
- 2. R291 and R293 value for Gladiator 1.2V core power
- 3. Route EMIF D[8:15] to exp connector (missed on RevB)
- Changes on RevD:
- 1. Added n_channel FET and RC to JTAG nTRST (P07)
- Changes on RevE:
- 1. Added n_channel FET and RC to JTAG nTRST (P07)
- 2. Replaced 2 color LEDs with 2 white LEDs
- Texas Instruments Inc
sheet 5
- If VCC_3.3V below 3.0V --> RESET
- This is the
  RESET pin rather
  than TRST
- If VCC_3.3V below 3.0V --> RESET
- If VCC_1.5V below 1.35V --> RESET
- SENSE THRESHOLD FOR
  TPS3808G09 IS 0.840 VOLTS
sheet 9
- Left Top
- Top
- C
- Light Sensor
- Right Top
- Digikey No: 490-2430-1-ND
- Digikey NO: 751-1055-1-ND
- E
- 0603
- Right Bottom
- At 25degree, R254=100k, at
  80degree, R254 is around
  1/10*100K=10K
- So no amplifier is needed
- Bottom
- Left Bottom
- Left
- Right
- CD is  the
  Right-Bottom Leg (top
  view)
sheet 10
- Vout = (1+R1/R2)*1.204
- For Vout=1.2V, R291 shorted, and R293 Open
- For Vout=1.5, R291=23.2Kohms, and R293=95.3Kohms
- R281: ERJ-2RKF2322X
- Default is 3.3V
- 5V or 3.3V
- R1x
- use jumper to select 3V
- For 3.3V
- For 5V
- R2x
- R2x
- V Reference is 1.25
- Vout = 1.25*(1+R2x/R1x)
sheet 11
- Foot Print Only
- Pin39/40/41/42/43 are the central GND
- AMP  2-5767004-2
  Receptacle, Center Strip Contacts
- Foot Print Only
